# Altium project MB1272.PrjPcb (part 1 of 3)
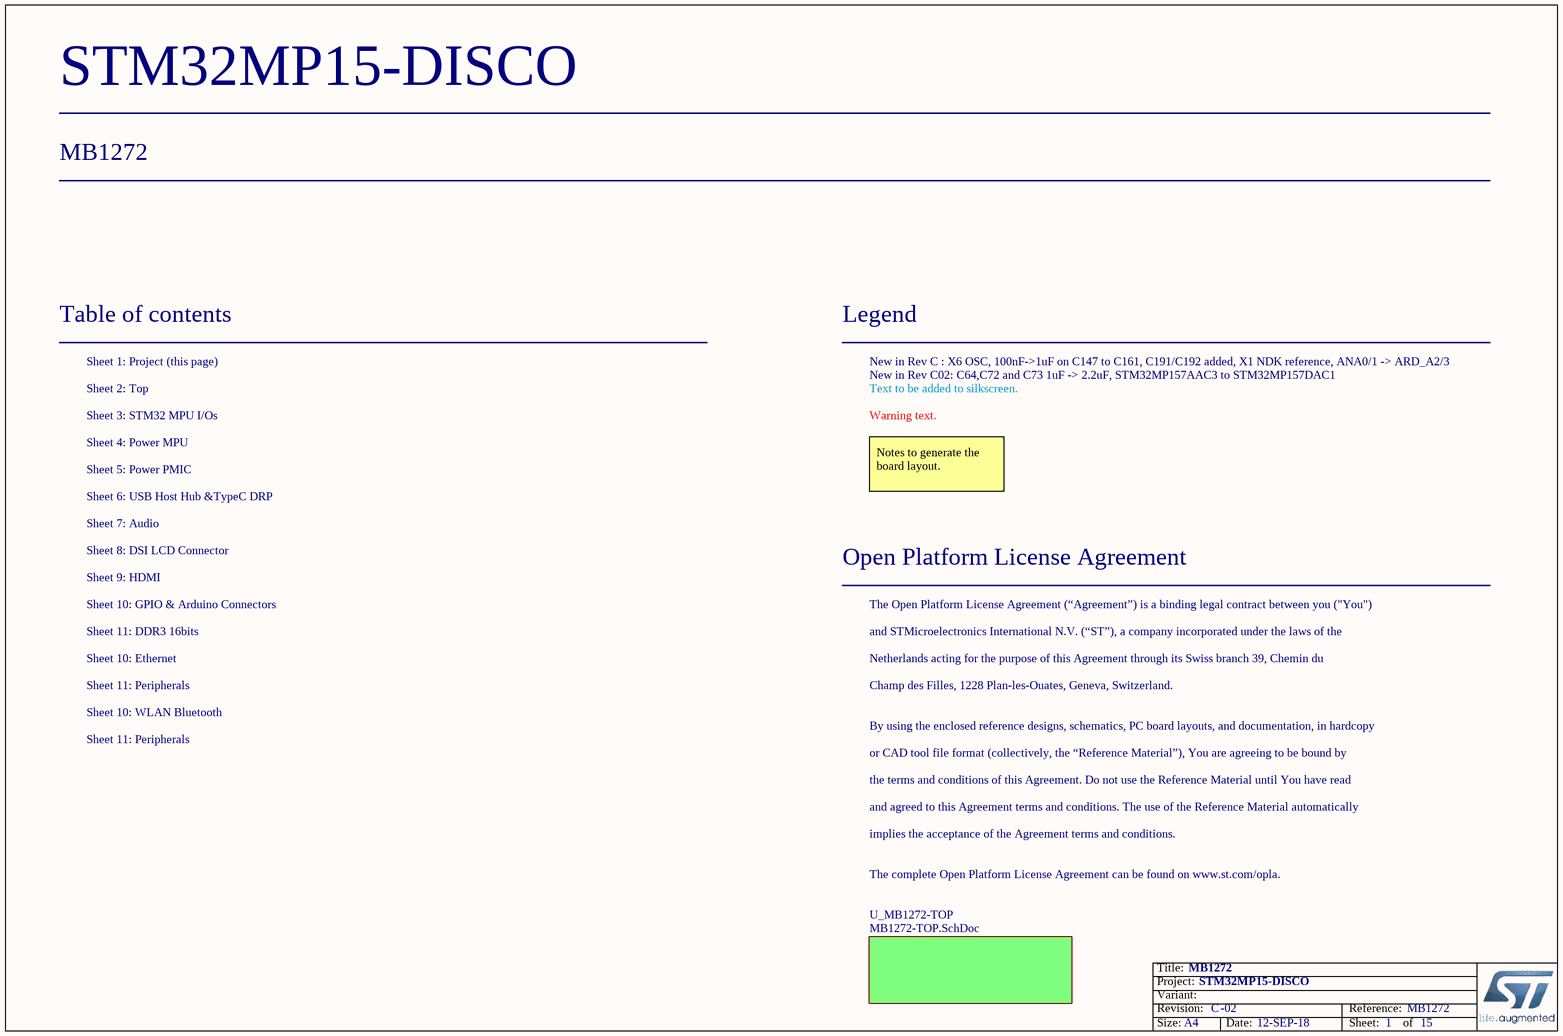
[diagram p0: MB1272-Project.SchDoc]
Board_Reference: MB1272; Board_PCB_Revision: C; Board_Name: STM32MP15-DISCO; Board_Document_Date: 12-SEP-18; Board_Assembly_Revision: 02
15 sheets, 519 parts. Net scope: flat (ports and power ports of the same name join across sheets).
Board file: MB1272C.PcbDoc
Sheets:
  MB1272-Project.SchDoc
    U_MB1272-TOP = MB1272-TOP.SchDoc
      U_Power_PMIC = Power_PMIC.SchDoc
      U_Power_MPU = Power_MPU.SchDoc
      U_MPU_12x12 = MPU_12x12.SchDoc
      U_Peripherals = Peripherals.SchDoc
      U_ST_LINK_V2-1 = ST_LINK_V2-1.SCHDOC
      U_GPIO_&_Arduino_ Connectors = GPIO_&_Arduino_ Connectors.SchDoc
      U_DSI_LCD = DSI_LCD.SchDoc
      U_WLAN_BLUETOOTH = WLAN_BLUETOOTH.SchDoc
      U_Ethernet = Ethernet.SchDoc
      U_HDMI = HDMI.SchDoc
      U_USB_Host_Hub&TypeC_DRP = USB_Host_Hub&TypeC_DRP.SchDoc
      U_AUDIO = AUDIO.SchDoc
      U_DDR3_16bits = DDR3_16bits.SchDoc

## Sheet MB1272-Project.SchDoc: MB1272
size A4; Date: Not used; ApprovedBy: Not used; CheckedBy: Not used; Author: Not used; CompanyName: STMicroelectronics; DrawnBy: Not used; Engineer: Not used; Organization: Not used; Address1: Not used; Address2: Not used; Address3: Not used; Address4: Not used; DocumentNumber: Not used; Revision: Not used; SheetNumber: 1; SheetTotal: 15

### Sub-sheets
U_MB1272-TOP = MB1272-TOP.SchDoc: no entries

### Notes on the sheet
- Table of contents
- Sheet 1: Project (this page)
- Legend
- New in Rev C : X6 OSC, 100nF->1uF on C147 to C161, C191/C192 added, X1 NDK reference, ANA0/1 -> ARD_A2/3
- New in Rev C02: C64,C72 and C73 1uF -> 2.2uF, STM32MP157AAC3 to STM32MP157DAC1
- Sheet 2: Top
- Sheet 3: STM32 MPU I/Os
- Sheet 4: Power MPU
- Text to be added to silkscreen.
- Warning text.
- Sheet 6: USB Host Hub &TypeC DRP
- Sheet 5: Power PMIC
- Notes to generate the board layout.
- Sheet 7: Audio
- Sheet 9: HDMI
- Sheet 8: DSI LCD Connector
- Open Platform License Agreement
- Sheet 10: GPIO & Arduino Connectors
- Sheet 11: DDR3 16bits
- The Open Platform License Agreement (“Agreement”) is a binding legal contract between you ("You")
- and STMicroelectronics International N.V. (“ST”), a company incorporated under the laws of the
- Sheet 10: Ethernet
- Sheet 11: Peripherals
- Sheet 10: WLAN Bluetooth
- Netherlands acting for the purpose of this Agreement through its Swiss branch 39, Chemin du
- Champ des Filles, 1228 Plan-les-Ouates, Geneva, Switzerland.
- By using the enclosed reference designs, schematics, PC board layouts, and documentation, in hardcopy
- or CAD tool file format (collectively, the “Reference Material”), You are agreeing to be bound by
- the terms and conditions of this Agreement. Do not use the Reference Material until You have read
- and agreed to this Agreement terms and conditions. The use of the Reference Material automatically
- implies the acceptance of the Agreement terms and conditions.
- The complete Open Platform License Agreement can be found on www.st.com/opla.

## Sheet MB1272-TOP.SchDoc: MB1272-TOP
size A4; CompanyName: STMicroelectronics; DocumentNumber: MB1272; Revision: B-01; SheetNumber: 2; SheetTotal: 15; Project: STM32MP15-DISCO PI
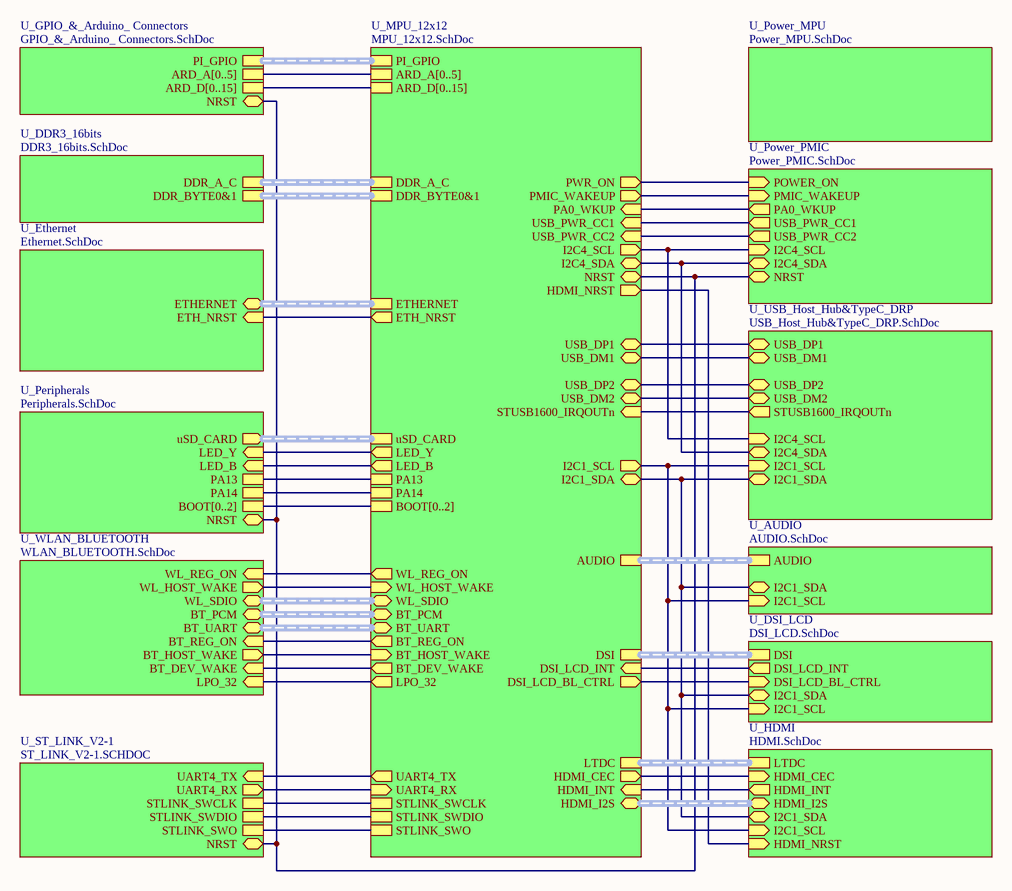
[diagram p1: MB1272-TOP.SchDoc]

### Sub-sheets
U_AUDIO = AUDIO.SchDoc: I2C1_SCL (in), I2C1_SDA (bidir), AUDIO (harness AUDIO)
U_DDR3_16bits = DDR3_16bits.SchDoc: DDR_A_C (harness DDR_A_C), DDR_BYTE0&1 (harness DDR_BYTE_0&1)
U_DSI_LCD = DSI_LCD.SchDoc: DSI (harness DSI), I2C1_SDA (bidir), I2C1_SCL (in), DSI_LCD_BL_CTRL (in), DSI_LCD_INT (out)
U_Ethernet = Ethernet.SchDoc: ETHERNET (harness ETHERNET), ETH_NRST (in)
U_GPIO_&_Arduino_ Connectors = GPIO_&_Arduino_ Connectors.SchDoc: NRST (bidir), ARD_A[0..5], ARD_D[0..15], PI_GPIO (harness PI_GPIO)
U_HDMI = HDMI.SchDoc: LTDC (harness LTDC), HDMI_CEC (in), I2C1_SDA (bidir), HDMI_INT (out), I2C1_SCL (in), HDMI_I2S (harness HDMI_I2S), HDMI_NRST (in)
U_MPU_12x12 = MPU_12x12.SchDoc: DDR_BYTE0&1 (harness DDR_BYTE_0&1), DDR_A_C (harness DDR_A_C), STLINK_SWDIO, STLINK_SWCLK, STLINK_SWO, UART4_TX (out), UART4_RX (in), PA13, PA14, PI_GPIO (harness PI_GPIO), ETHERNET (harness ETHERNET), AUDIO (harness AUDIO), PMIC_WAKEUP (out), PA0_WKUP (in), NRST (bidir), PWR_ON (out), I2C4_SCL (out), I2C4_SDA (bidir), DSI (harness DSI), LTDC (harness LTDC), HDMI_CEC (out), uSD_CARD (harness uSD_CARD), BOOT[0..2], ARD_A[0..5], ARD_D[0..15], I2C1_SDA (bidir), I2C1_SCL (out), USB_DM1 (bidir), USB_DM2 (bidir), USB_DP2 (bidir), USB_DP1 (bidir), DSI_LCD_BL_CTRL (out), DSI_LCD_INT (in), HDMI_INT (in), WL_SDIO (harness WLAN_SDIO), BT_PCM (harness BT_PCM), BT_UART (harness BT_UART), BT_REG_ON (out), BT_HOST_WAKE (in), WL_REG_ON (out), BT_DEV_WAKE (out), WL_HOST_WAKE (in), HDMI_I2S (harness HDMI_I2S), STUSB1600_IRQOUTn (in), LPO_32 (out), USB_PWR_CC1 (in), USB_PWR_CC2 (in), LED_Y (out), LED_B (out), HDMI_NRST (out), ETH_NRST (out)
U_Peripherals = Peripherals.SchDoc: BOOT[0..2], PA13, PA14, NRST (bidir), uSD_CARD (harness uSD_CARD), LED_B (in), LED_Y (in)
U_Power_MPU = Power_MPU.SchDoc: no entries
U_Power_PMIC = Power_PMIC.SchDoc: I2C4_SDA (bidir), I2C4_SCL (in), PA0_WKUP (out), NRST (bidir), POWER_ON (in), PMIC_WAKEUP (in), USB_PWR_CC1 (out), USB_PWR_CC2 (out)
U_ST_LINK_V2-1 = ST_LINK_V2-1.SCHDOC: NRST (bidir), STLINK_SWO, STLINK_SWDIO, STLINK_SWCLK, UART4_RX (out), UART4_TX (in)
U_USB_Host_Hub&TypeC_DRP = USB_Host_Hub&TypeC_DRP.SchDoc: USB_DP1 (bidir), USB_DM1 (bidir), I2C1_SDA (bidir), I2C1_SCL (in), STUSB1600_IRQOUTn (out), I2C4_SCL (in), I2C4_SDA (bidir), USB_DM2 (bidir), USB_DP2 (bidir)
U_WLAN_BLUETOOTH = WLAN_BLUETOOTH.SchDoc: WL_SDIO (harness WLAN_SDIO), BT_UART (harness BT_UART), BT_PCM (harness BT_PCM), BT_REG_ON (in), BT_HOST_WAKE (out), WL_REG_ON (in), BT_DEV_WAKE (in), WL_HOST_WAKE (out), LPO_32 (in)

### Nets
(unnamed): sheet U_Power_PMIC/I2C4_SDA, sheet U_MPU_12x12/I2C4_SDA, sheet U_USB_Host_Hub&TypeC_DRP/I2C4_SDA
(unnamed): sheet U_Power_PMIC/I2C4_SCL, sheet U_MPU_12x12/I2C4_SCL, sheet U_USB_Host_Hub&TypeC_DRP/I2C4_SCL  [a separate net that carries the same name]
(unnamed): sheet U_Power_PMIC/PA0_WKUP, sheet U_MPU_12x12/PA0_WKUP  [a separate net that carries the same name]
(unnamed): sheet U_Power_PMIC/NRST, sheet U_MPU_12x12/NRST, sheet U_Peripherals/NRST, sheet U_ST_LINK_V2-1/NRST, sheet U_GPIO_&_Arduino_ Connectors/NRST  [a separate net that carries the same name]
(unnamed): sheet U_Power_PMIC/POWER_ON, sheet U_MPU_12x12/PWR_ON  [a separate net that carries the same name]
(unnamed): sheet U_Power_PMIC/PMIC_WAKEUP, sheet U_MPU_12x12/PMIC_WAKEUP  [a separate net that carries the same name]
(unnamed): sheet U_Power_PMIC/USB_PWR_CC1, sheet U_MPU_12x12/USB_PWR_CC1  [a separate net that carries the same name]
(unnamed): sheet U_Power_PMIC/USB_PWR_CC2, sheet U_MPU_12x12/USB_PWR_CC2  [a separate net that carries the same name]
(unnamed): sheet U_MPU_12x12/STLINK_SWDIO, sheet U_ST_LINK_V2-1/STLINK_SWDIO  [a separate net that carries the same name]
(unnamed): sheet U_MPU_12x12/STLINK_SWCLK, sheet U_ST_LINK_V2-1/STLINK_SWCLK  [a separate net that carries the same name]
(unnamed): sheet U_MPU_12x12/STLINK_SWO, sheet U_ST_LINK_V2-1/STLINK_SWO  [a separate net that carries the same name]
(unnamed): sheet U_MPU_12x12/UART4_TX, sheet U_ST_LINK_V2-1/UART4_TX  [a separate net that carries the same name]
(unnamed): sheet U_MPU_12x12/UART4_RX, sheet U_ST_LINK_V2-1/UART4_RX  [a separate net that carries the same name]
(unnamed): sheet U_MPU_12x12/PA13, sheet U_Peripherals/PA13  [a separate net that carries the same name]
(unnamed): sheet U_MPU_12x12/PA14, sheet U_Peripherals/PA14  [a separate net that carries the same name]
(unnamed): sheet U_MPU_12x12/HDMI_CEC, sheet U_HDMI/HDMI_CEC  [a separate net that carries the same name]
(unnamed): sheet U_MPU_12x12/I2C1_SDA, sheet U_DSI_LCD/I2C1_SDA, sheet U_HDMI/I2C1_SDA, sheet U_USB_Host_Hub&TypeC_DRP/I2C1_SDA, sheet U_AUDIO/I2C1_SDA  [a separate net that carries the same name]
(unnamed): sheet U_MPU_12x12/I2C1_SCL, sheet U_DSI_LCD/I2C1_SCL, sheet U_HDMI/I2C1_SCL, sheet U_USB_Host_Hub&TypeC_DRP/I2C1_SCL, sheet U_AUDIO/I2C1_SCL  [a separate net that carries the same name]
(unnamed): sheet U_MPU_12x12/USB_DM1, sheet U_USB_Host_Hub&TypeC_DRP/USB_DM1  [a separate net that carries the same name]
(unnamed): sheet U_MPU_12x12/USB_DM2, sheet U_USB_Host_Hub&TypeC_DRP/USB_DM2  [a separate net that carries the same name]
(unnamed): sheet U_MPU_12x12/USB_DP2, sheet U_USB_Host_Hub&TypeC_DRP/USB_DP2  [a separate net that carries the same name]
(unnamed): sheet U_MPU_12x12/USB_DP1, sheet U_USB_Host_Hub&TypeC_DRP/USB_DP1  [a separate net that carries the same name]
(unnamed): sheet U_MPU_12x12/DSI_LCD_BL_CTRL, sheet U_DSI_LCD/DSI_LCD_BL_CTRL  [a separate net that carries the same name]
(unnamed): sheet U_MPU_12x12/DSI_LCD_INT, sheet U_DSI_LCD/DSI_LCD_INT  [a separate net that carries the same name]
(unnamed): sheet U_MPU_12x12/HDMI_INT, sheet U_HDMI/HDMI_INT  [a separate net that carries the same name]
(unnamed): sheet U_MPU_12x12/BT_REG_ON, sheet U_WLAN_BLUETOOTH/BT_REG_ON  [a separate net that carries the same name]
(unnamed): sheet U_MPU_12x12/BT_HOST_WAKE, sheet U_WLAN_BLUETOOTH/BT_HOST_WAKE  [a separate net that carries the same name]
(unnamed): sheet U_MPU_12x12/WL_REG_ON, sheet U_WLAN_BLUETOOTH/WL_REG_ON  [a separate net that carries the same name]
(unnamed): sheet U_MPU_12x12/BT_DEV_WAKE, sheet U_WLAN_BLUETOOTH/BT_DEV_WAKE  [a separate net that carries the same name]
(unnamed): sheet U_MPU_12x12/WL_HOST_WAKE, sheet U_WLAN_BLUETOOTH/WL_HOST_WAKE  [a separate net that carries the same name]
(unnamed): sheet U_MPU_12x12/STUSB1600_IRQOUTn, sheet U_USB_Host_Hub&TypeC_DRP/STUSB1600_IRQOUTn  [a separate net that carries the same name]
(unnamed): sheet U_MPU_12x12/LPO_32, sheet U_WLAN_BLUETOOTH/LPO_32  [a separate net that carries the same name]
(unnamed): sheet U_MPU_12x12/LED_Y, sheet U_Peripherals/LED_Y  [a separate net that carries the same name]
(unnamed): sheet U_MPU_12x12/LED_B, sheet U_Peripherals/LED_B  [a separate net that carries the same name]
(unnamed): sheet U_MPU_12x12/HDMI_NRST, sheet U_HDMI/HDMI_NRST  [a separate net that carries the same name]
(unnamed): sheet U_MPU_12x12/ETH_NRST, sheet U_Ethernet/ETH_NRST  [a separate net that carries the same name]

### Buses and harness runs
bus sheet U_GPIO_&_Arduino_ Connectors/ARD_A[0..5] = sheet U_MPU_12x12/ARD_A[0..5]
bus sheet U_GPIO_&_Arduino_ Connectors/ARD_D[0..15] = sheet U_MPU_12x12/ARD_D[0..15]
bus sheet U_MPU_12x12/BOOT[0..2] = sheet U_Peripherals/BOOT[0..2]
harness sheet U_AUDIO/AUDIO = sheet U_MPU_12x12/AUDIO
harness sheet U_DDR3_16bits/DDR_A_C = sheet U_MPU_12x12/DDR_A_C
harness sheet U_DDR3_16bits/DDR_BYTE0&1 = sheet U_MPU_12x12/DDR_BYTE0&1
harness sheet U_DSI_LCD/DSI = sheet U_MPU_12x12/DSI
harness sheet U_Ethernet/ETHERNET = sheet U_MPU_12x12/ETHERNET
harness sheet U_GPIO_&_Arduino_ Connectors/PI_GPIO = sheet U_MPU_12x12/PI_GPIO
harness sheet U_HDMI/HDMI_I2S = sheet U_MPU_12x12/HDMI_I2S
harness sheet U_HDMI/LTDC = sheet U_MPU_12x12/LTDC
harness sheet U_MPU_12x12/BT_PCM = sheet U_WLAN_BLUETOOTH/BT_PCM
harness sheet U_MPU_12x12/BT_UART = sheet U_WLAN_BLUETOOTH/BT_UART
harness sheet U_MPU_12x12/uSD_CARD = sheet U_Peripherals/uSD_CARD
harness sheet U_MPU_12x12/WL_SDIO = sheet U_WLAN_BLUETOOTH/WL_SDIO

## Sheet Power_PMIC.SchDoc: Power_PMIC
size A3; Date: 01-DEC-2013; CompanyName: STMicroelectronics; Organization: Microcontrollers Division; Address1: 12, Rue Jules HOROWITZ; Address2: 38019 Grenoble; Address3: FRANCE; DocumentNumber: MB1272; Revision: A-01; SheetNumber: 5; SheetTotal: 15; Project: STM32MP15-DISCO PI
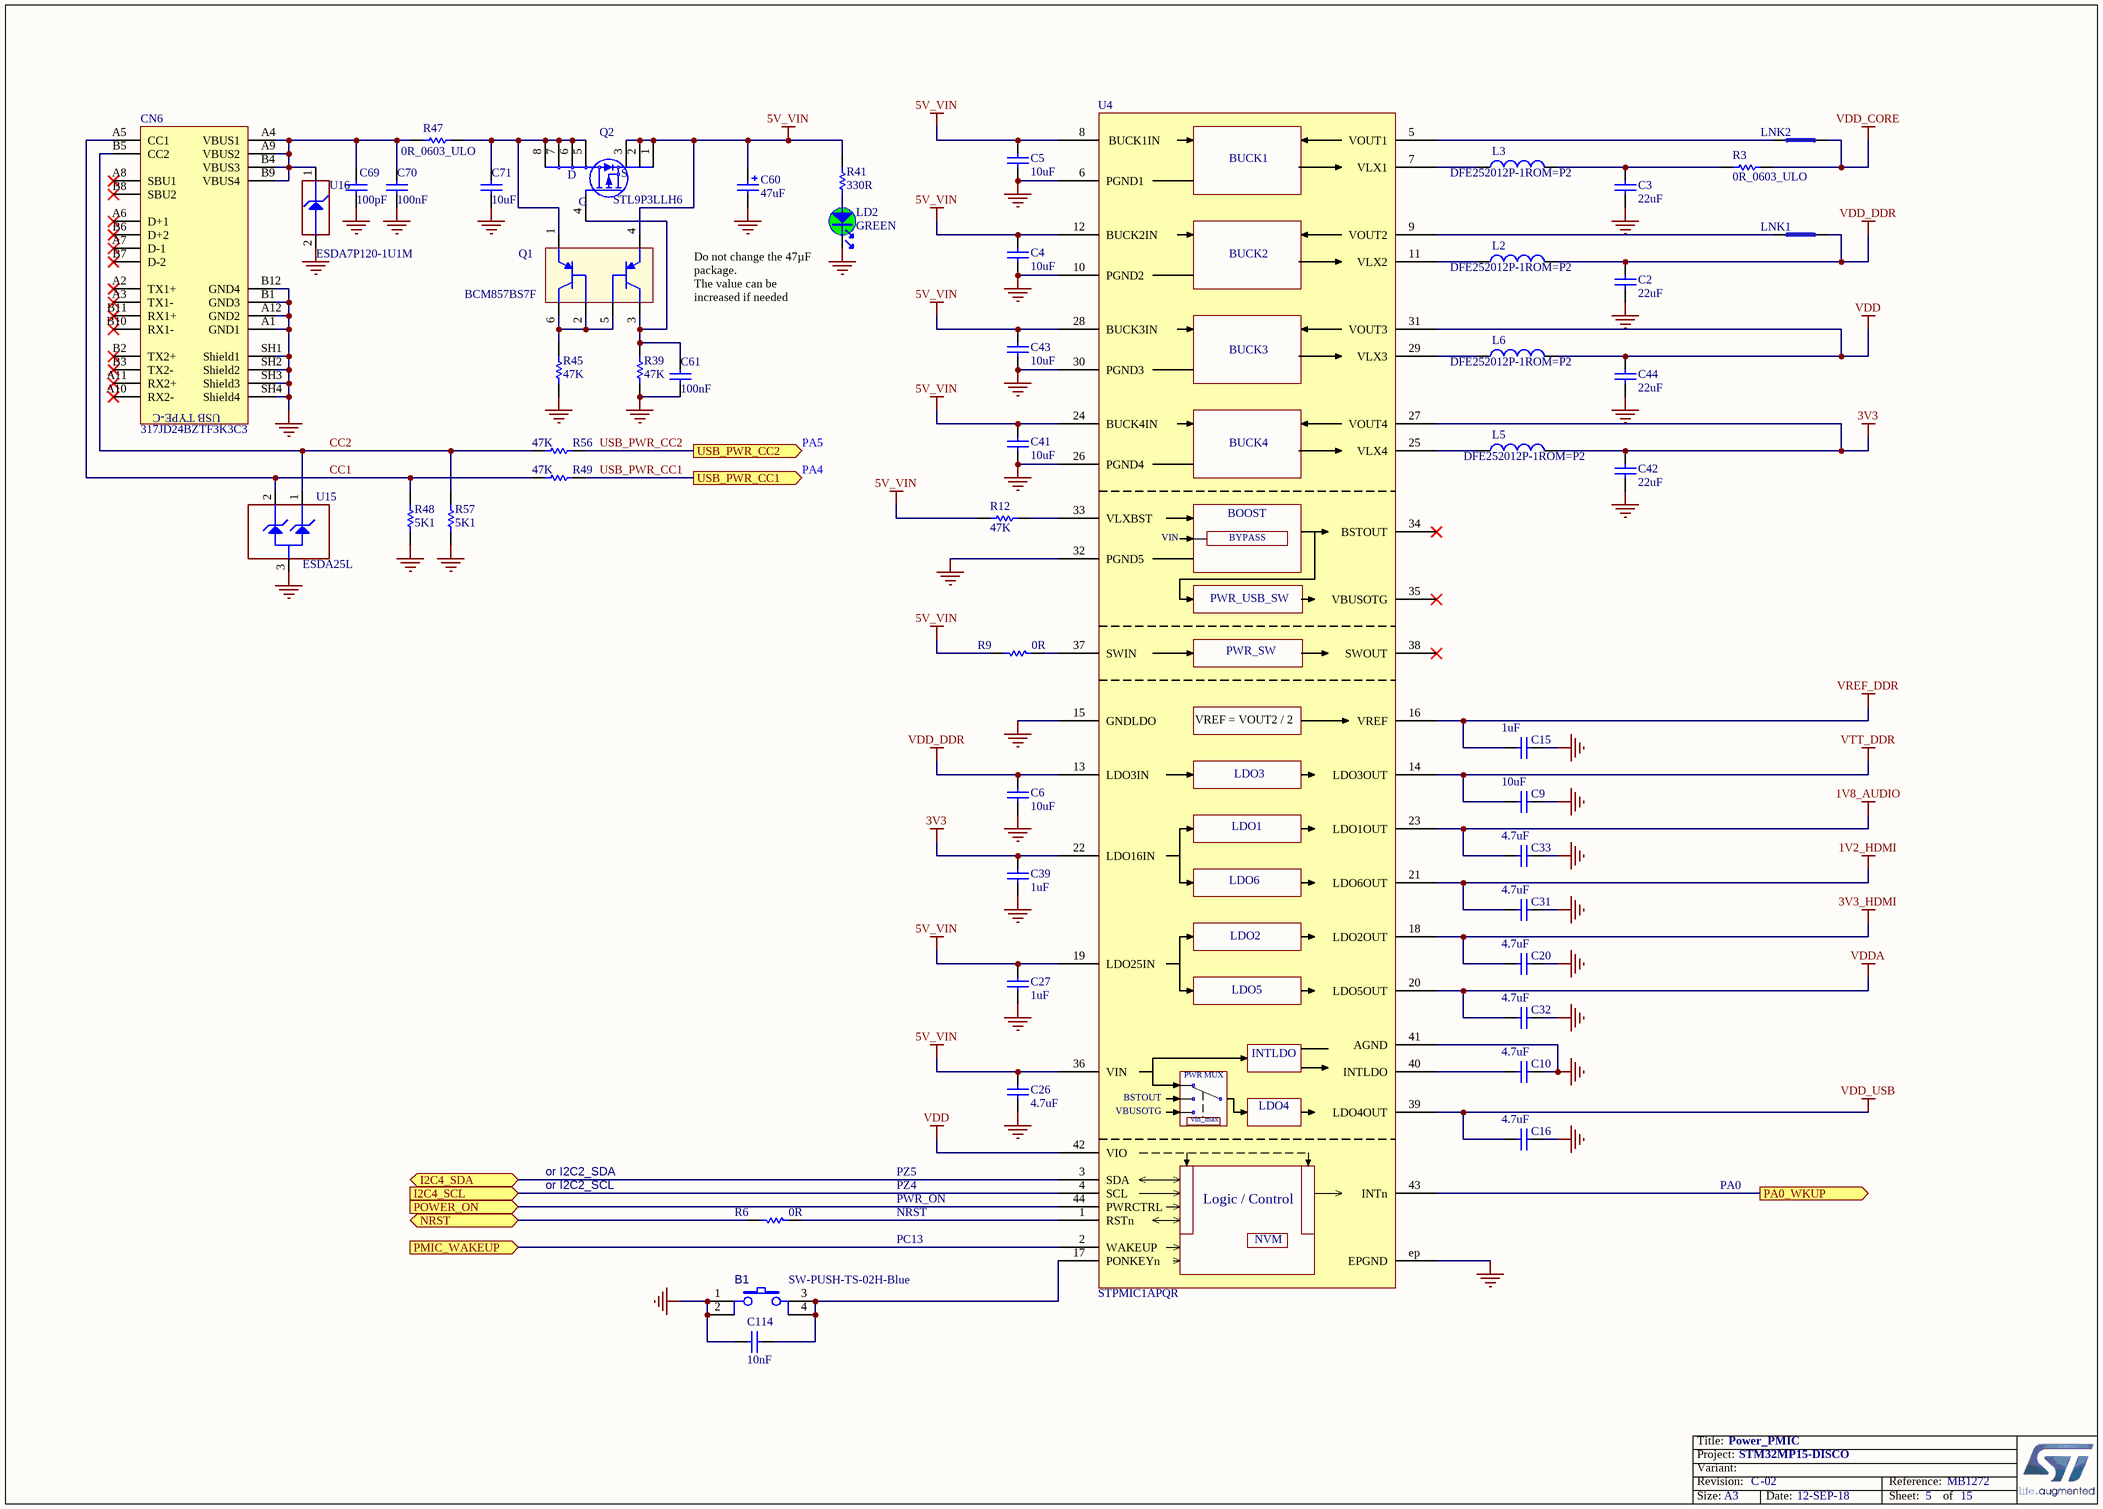
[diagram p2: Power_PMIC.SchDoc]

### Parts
B1  value SW-PUSH-TS-02H-Blue  [SWI_JIUBABA_C-TS-02H-2-5-B-V-T_R_BLUE]
C2  value 22uF  [C0603]
C3  value 22uF  [C0603]
C4  value 10uF  [C0603]
C5  value 10uF  [C0603]
C6  value 10uF  [C0603]
C9  value 10uF  [C0603]
C10  value 4.7uF  [C0402]  (hidden comment: Capacitor)
C15  value 1uF  [C0402]
C16  value 4.7uF  [C0402]  (hidden comment: Capacitor)
C20  value 4.7uF  [C0402]  (hidden comment: Capacitor)
C26  value 4.7uF  [C0402]  (hidden comment: Capacitor)
C27  value 1uF  [C0402]
C31  value 4.7uF  [C0402]  (hidden comment: Capacitor)
C32  value 4.7uF  [C0402]  (hidden comment: Capacitor)
C33  value 4.7uF  [C0402]  (hidden comment: Capacitor)
C39  value 1uF  [C0402]
C41  value 10uF  [C0603]
C42  value 22uF  [C0603]
C43  value 10uF  [C0603]
C44  value 22uF  [C0603]
C60  value 47uF  [CPOL_TAJ-C_2312_H2P6]  (hidden comment: Cap_POL_TANA)
C61  value 100nF  [C0402]
C69  value 100pF  [C0402]  (hidden comment: Capacitor)
C70  value 100nF  [C0402]
C71  value 10uF  [C0805]  (hidden comment: Capacitor)
C114  value 10nF  [C0402]
CN6  value 317JD24BZTF3K3C3  [CON_USB-TYPEC_COXOC_317JD24BZTF3K3C3]
L2  Manufacturer_Part_Number: DFE252012P-1ROM=P2  [IND_2520_TOKO_DFE252012P]  (hidden comment: IND_1uH_42mohm_3.2A)
L3  Manufacturer_Part_Number: DFE252012P-1ROM=P2  [IND_2520_TOKO_DFE252012P]  (hidden comment: IND_1uH_42mohm_3.2A)
L5  Manufacturer_Part_Number: DFE252012P-1ROM=P2  [IND_2520_TOKO_DFE252012P]  (hidden comment: IND_1uH_42mohm_3.2A)
L6  Manufacturer_Part_Number: DFE252012P-1ROM=P2  [IND_2520_TOKO_DFE252012P]  (hidden comment: IND_1uH_42mohm_3.2A)
LD2  value GREEN  [LED_0603_GREEN]
LNK1  link_200  [LINK200]  (value not drawn)  (no BOM)
LNK2  link_200  [LINK200]  (value not drawn)  (no BOM)
Q1  value BCM857BS7F  [DIO_SOT363]
Q2  value STL9P3LLH6  [MOS_POWERFLAT_3P3X3P3_P065]
R3  value 0R_0603_ULO  [R0603]
R6  value 0R  [R0402]
R9  value 0R  [R0402]
R12  value 47K  [R0402]  (hidden comment: Resistor)
R39  value 47K  [R0402]  (hidden comment: Resistor)
R41  value 330R  [R0402]
R45  value 47K  [R0402]  (hidden comment: Resistor)
R47  value 0R_0603_ULO  [R0603]
R48  value 5K1  [R0402]  (hidden comment: Resistor)
R49  value 47K  [R0402]  (hidden comment: Resistor)
R56  value 47K  [R0402]  (hidden comment: Resistor)
R57  value 5K1  [R0402]  (hidden comment: Resistor)
U4  value STPMIC1APQR  [ICC_WFQFN44-EPAD_5X6_P040]  (hidden comment: STPMU1)
U15  value ESDA25L  [ESD_SOT23]  (hidden comment: New schematic symbol : correction 2 diodes instead of one)
U16  value ESDA7P120-1U1M  [ESD_QFN1610_2N_1K_2A]  (hidden comment: ​Footprint needed DFN105P160X60-2N)

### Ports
I2C4_SCL (in), I2C4_SDA (bidir), NRST (bidir), PA0_WKUP (out), PMIC_WAKEUP (in), POWER_ON (in), USB_PWR_CC1 (out), USB_PWR_CC2 (out)

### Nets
1V2_HDMI: C31.2 U4.21(LDO6OUT)
1V8_AUDIO: C33.2 U4.23(LDO1OUT)
3V3: C39.2 C42.2 L5.2 U4.22(LDO16IN) U4.27(VOUT4)
3V3_HDMI: C20.2 U4.18(LDO2OUT)
5V_VIN: C4.2 C5.2 C26.2 C27.2 C41.2 C43.2 C60.1 Q1.4(E2) Q2.1(S) Q2.2(S) Q2.3(S) R9.1 R12.2 R41.2 U4.8(BUCK1IN) U4.12(BUCK2IN) U4.19(LDO25IN) U4.24(BUCK4IN) U4.28(BUCK3IN) U4.36(VIN)
GND: B1.1 B1.2 C2.1 C3.1 C4.1 C5.1 C6.1 C9.1 C10.2 C15.1 C16.1 C20.1 C26.1 C27.1 C31.1 C32.1 C33.1 C39.1 C41.1 C42.1 C43.1 C44.1 C60.2 C61.2 C69.1 C70.2 C71.1 C114.1 CN6.A1(GND1) CN6.A12(GND2) CN6.B1(GND3) CN6.B12(GND4) CN6.SH1(Shield1) CN6.SH2(Shield2) CN6.SH3(Shield3) CN6.SH4(Shield4) LD2.2 R39.1 R45.1 R48.1 R57.1 U4.6(PGND1) U4.10(PGND2) U4.15(GNDLDO) U4.26(PGND4) U4.30(PGND3) U4.32(PGND5) U4.41(AGND) U4.ep(EPGND) U15.3(GND) U16.2(GND)
VDD: C44.2 L6.2 U4.31(VOUT3) U4.42(VIO)
VDD_CORE: LNK2.2 R3.2
VDD_DDR: C2.2 C6.2 L2.2 LNK1.2 U4.13(LDO3IN)
VDD_USB: C16.2 U4.39(LDO4OUT)
VDDA: C32.2 U4.20(LDO5OUT)
VREF_DDR: C15.2 U4.16(VREF)
VTT_DDR: C9.2 U4.14(LDO3OUT)
CC1: CN6.A5(CC1) R48.2 R49.1 U15.2(IO2)
CC2: CN6.B5(CC2) R56.1 R57.2 U15.1(IO1)
I2C4_SCL: U4.4(SCL) ; port I2C4_SCL
I2C4_SDA: U4.3(SDA) ; port I2C4_SDA
NRST: R6.1 ; port NRST
PA0_WKUP: U4.43(INTn) ; port PA0_WKUP
PMIC_WAKEUP: U4.2(WAKEUP) ; port PMIC_WAKEUP
USB_PWR_CC1: R49.2 ; port USB_PWR_CC1
USB_PWR_CC2: R56.2 ; port USB_PWR_CC2
NetB1_3: B1.3 B1.4 C114.2 U4.17(PONKEYn)
NetC3_2: C3.2 L3.2 R3.1
NetC10_1: C10.1 U4.40(INTLDO)
NetC61_1: C61.1 Q1.3(C2) Q2.4(G) R39.2
NetC69_2: C69.2 C70.1 CN6.A4(VBUS1) CN6.A9(VBUS2) CN6.B4(VBUS3) CN6.B9(VBUS4) R47.1 U16.1(IO1)
NetC71_2: C71.2 Q1.1(E1) Q2.5(D) Q2.6(D) Q2.7(D) Q2.8(D) R47.2
NetL2_1: L2.1 U4.11(VLX2)
NetL3_1: L3.1 U4.7(VLX1)
NetL5_1: L5.1 U4.25(VLX4)
NetL6_1: L6.1 U4.29(VLX3)
NetLD2_1: LD2.1 R41.1
NetLNK1_1: LNK1.1 U4.9(VOUT2)
NetLNK2_1: LNK2.1 U4.5(VOUT1)
NetQ1_2: Q1.2(B1) Q1.5(B2) Q1.6(C1) R45.2
NetR6_2: R6.2 U4.1(RSTn)
NetR9_2: R9.2 U4.37(SWIN)
NetR12_1: R12.1 U4.33(VLXBST)
NetU4_44: U4.44(PWRCTRL) ; port POWER_ON

Not connected (* = marked no-connect by the designer): CN6 A2(TX1+)* A3(TX1-)* A6(D+1)* A7(D-1)* A8(SBU1)* A10(RX2-)* A11(RX2+)* B2(TX2+)* B3(TX2-)* B6(D+2)* B7(D-2)* B8(SBU2)* B10(RX1-)* B11(RX1+)*; U4 34(BSTOUT)* 35(VBUSOTG)* 38(SWOUT)*

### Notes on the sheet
- (near LD2) Do not change the 47µF package.
  The value can be increased if needed
- PA5
- PA4
- or I2C2_SDA
- or I2C2_SCL
- PZ5
- PZ4
- PA0
- NRST
- PWR_ON
- PC13

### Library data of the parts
B1 = MCD-00172: Switch HW SMD blue; Part_Type: Misc; Manufacturer_Part_Number: C-TS-02H-2.5-B-V-T/R BLUE; Manufacturer: JIUBABA; Provided_By: SUBCO; Initial_Board_Reference: MB1264
C2 C3 C42 C44 = MCD-00100: Capacitor, MLCC, 22uF, 6V3, X5R, 20%, 0603, T=0,8mm; Manufacturer_Part_Number: GRM188R60J226MEA0J; Manufacturer: MURATA; ECCN_US: EAR99; ECCN_EU: NEC; Provided_By: SUBCO; Initial_Board_Reference: mb1262
C4-C6 C9 C41 C43 = MCD-00099: Capacitor, MLCC, 10uF, 10V, X5R, 10%, 0603, T=0,8mm; Manufacturer_Part_Number: GRM188R61A106KE69D; Manufacturer: MURATA; ECCN_US: EAR99; ECCN_EU: NEC; Provided_By: SUBCO; Initial_Board_Reference: mb1262
C10 C16 C20 C26 C31-C33 = MCD-01356: Capacitor, MLCC, 4.7uF, 6V3, X5R, 20%, 0402, T=0,5mm; Manufacturer_Part_Number: GRM155R60J475ME47; Manufacturer: MURATA; Provided_By: SUBCO
C15 C27 C39 = MCD-00095: Capacitor, MLCC, 1uF, 6V3, X5R, 10%, 0402, T=0,5mm; Manufacturer_Part_Number: GRM155R61E105KA12; Manufacturer: MURATA; Alternate_Manufacturer_Part_Number: GRM155R60J105KE19; ECCN_US: EAR99; ECCN_EU: NEC; Provided_By: SUBCO; Initial_Board_Reference: mb1262
C60 = MCD-00559: Capacitor, Tantalum, 47uF, 16V, 10%, TypeC; Manufacturer_Part_Number: TAJC476K016RNJ; Manufacturer: AVX; Provided_By: SUBCO; Initial_Board_Reference: MB1331
C61 C70 = MCD-00006: Capacitor,100nF,16V,X7R,10%,0402; Manufacturer_Part_Number: CC0402KRX7R7BB104; Manufacturer: YAGEO; Alternate_Manufacturer: MURATA; Alternate_Manufacturer_Part_Number: GCM155R71C104KA55D; Provided_By: SUBCO; Initial_Board_Reference: mb1274
C69 = MCD-00205: Capacitor, MLCC, 100pF, 50V, NPO, 5%, 0402, T=0,5mm; Manufacturer_Part_Number: CC0402JRNPO9BN101; Manufacturer: YAGEO; Provided_By: SUBCO
C71 = MCD-00014: Capacitor, MLCC, 10uF, 25V, X5R, 10%, 0805, T=0,85mm; Manufacturer_Part_Number: CC0805KRX5R8BB106; Manufacturer: YAGEO; Provided_By: SUBCO; Initial_Board_Reference: MB1274
C114 = MCD-00011: Capacitor, MLCC, 10nF, 16V, X7R, 10%, 0402, T=0.5mm; Manufacturer_Part_Number: CC0402KRX7R7BB103; Manufacturer: YAGEO; Provided_By: SUBCO; Initial_Board_Reference: mb1274
CN6 = MCD-01108: USB tyce C certified receptacle for 1.6mm pcb height; Part_Type: Connector; Manufacturer: CHANT SINCERE (COXOC); ECCN_US: NA; Provided_By: SUBCO; Initial_Board_Reference: MB1272
L2 L3 L5 L6 = MCD-01122: Power Inductor ,1µH,4.3A max,+-20%,0.042ohm,2520; Manufacturer: MURATA; ECCN_US: EAR99; Provided_By: SUBCO; Initial_Board_Reference: MB1272
LD2 = MCD-00050: LED, Green, 0603; Part_Type: Display; Manufacturer_Part_Number: 19-213SYGC/S530-E2/TR8; Manufacturer: EVERLIGHT; ECCN_US: EAR99; ECCN_EU: NEC; Provided_By: SUBCO; Initial_Board_Reference: mb1274
LNK1 LNK2 = link_200: link 0.2mm
Q1 = MCD-01120: Transistor 45V Matched Pair PNP small Signal transistor in SOT363; Part_Type: IC; Manufacturer: DIODES_INC; Alternate_Manufacturer_Part_Number: NST45010MW6T1G; Alternate_Manufacturer: ONSEMI; Provided_By: SUBCO; Initial_Board_Reference: MB1272
Q2 = MCD-01126: Power Mosfet, P-channel,VDS -30V,RDS 12mohm typ,ID -9A; Part_Type: IC; Manufacturer: STMICROELECTRONICS; ECCN_US: EAR99; ECCN_EU: NEC; Provided_By: SUBCO with ST control; Initial_Board_Reference: MB1272
R3 R47 = MCD-00181: Resistor,0R,0603,ULO; Manufacturer_Part_Number: PMR03EZPJ000; Manufacturer: ROHM; Provided_By: SUBCO
R6 R9 = MCD-00052: Resistor,0R,0402,5%,1/16W; Manufacturer_Part_Number: RC0402JR-070RL; Manufacturer: YAGEO; Provided_By: SUBCO; Initial_Board_Reference: mb1274
R12 R39 R45 R49 R56 = MCD-00063: Resistor,47K,0402,1%,1/16W; Manufacturer_Part_Number: RC0402FR-0747KL; Manufacturer: YAGEO; Provided_By: SUBCO; Initial_Board_Reference: MB1274
R41 = MCD-00062: Resistor,330R,0402,1%,1/16W; Manufacturer_Part_Number: RC0402FR-07330RL; Manufacturer: YAGEO; Provided_By: SUBCO; Initial_Board_Reference: mb1274
R48 R57 = MCD-00333: Resistor,5K1,0402,1%,1/16W; Manufacturer_Part_Number: RC0402FR-075K1L; Manufacturer: YAGEO; Provided_By: SUBCO; Initial_Board_Reference: MB1272
U4 = MCD-01650: ST PMIC:  4 step-down + 1 advanced boost SMPS, 6 LDOs, 2 pwr switches, DDR Vref, NVM option 'A' for IO@3.3V; Part_Type: IC; Manufacturer: STMICROELECTRONICS; Provided_By: SUBCO with ST control
U15 = MCD-01125: DUAL TRANSIL ARRAY FOR ESD PROTECTION; Part_Type: Diode; Manufacturer: STMICROELECTRONICS; BMS_Part_Number: 9151131; ECCN_US: EAR99; ECCN_EU: NEC; Provided_By: SUBCO with ST control; Initial_Board_Reference: MB1272
U16 = MCD-01026: High power transient voltage suppressor; Part_Type: Diode; Manufacturer: STMICROELECTRONICS; BMS_Part_Number: 9179046; ECCN_US: EAR99; ECCN_EU: NEC; Provided_By: SUBCO with ST control; Initial_Board_Reference: MB1378

## Sheet Power_MPU.SchDoc: Power_MPU
size A3; CompanyName: STMicroelectronics; DocumentNumber: MB1272; Revision: A-01; SheetNumber: 4; SheetTotal: 15; Project: STM32MP15-DISCO PI
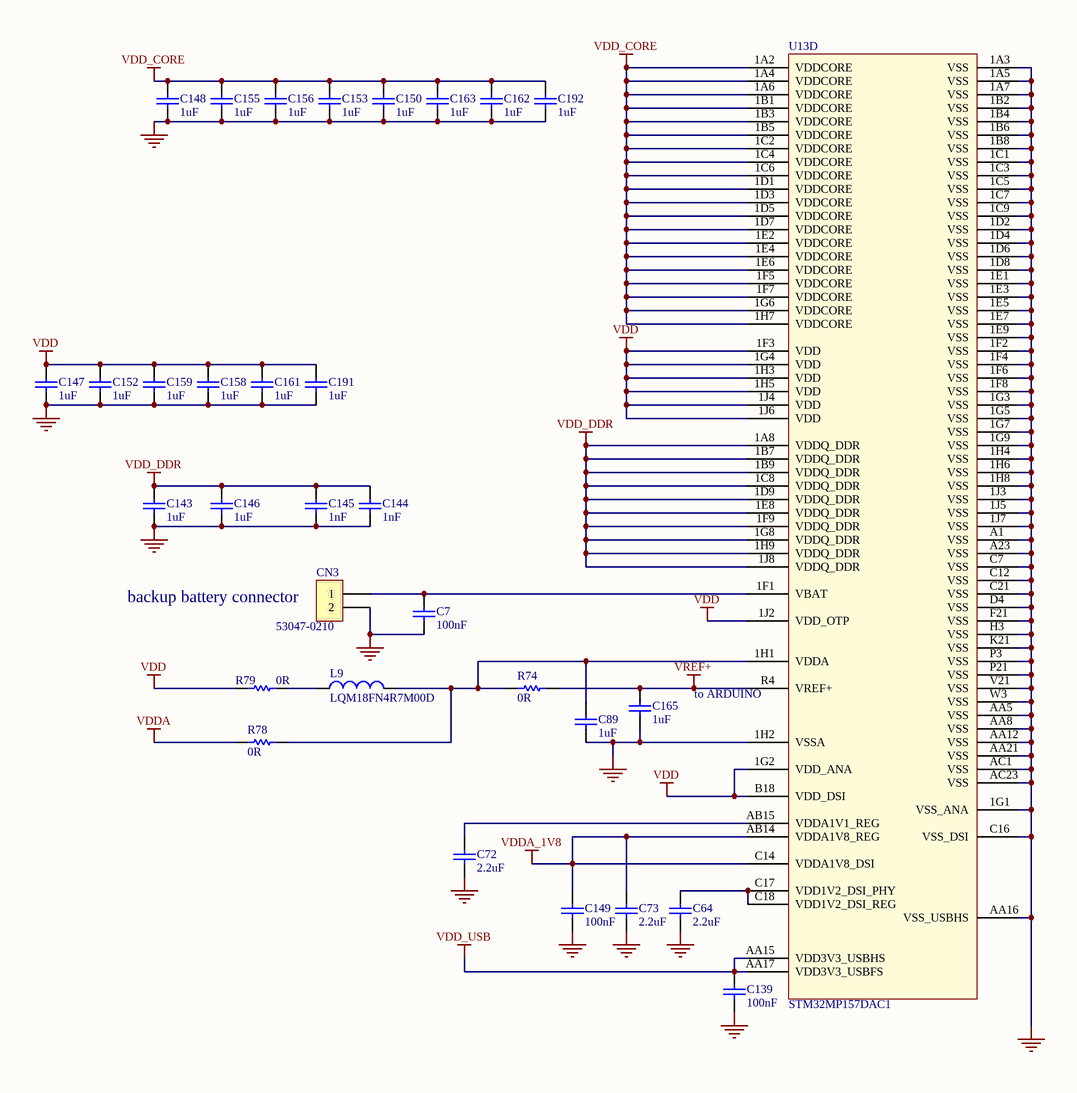
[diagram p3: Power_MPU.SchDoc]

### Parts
C7  value 100nF  [C0402]
C64  value 2.2uF  [C0402]  (hidden comment: Capacitor)
C72  value 2.2uF  [C0402]  (hidden comment: Capacitor)
C73  value 2.2uF  [C0402]  (hidden comment: Capacitor)
C89  value 1uF  [C0402]
C139  value 100nF  [C0402]
C143  value 1uF  [C0402]
C144  value 1nF  [C0402]
C145  value 1nF  [C0402]
C146  value 1uF  [C0402]
C147  value 1uF  [C0402]
C148  value 1uF  [C0402]
C149  value 100nF  [C0402]
C150  value 1uF  [C0402]
C152  value 1uF  [C0402]
C153  value 1uF  [C0402]
C155  value 1uF  [C0402]
C156  value 1uF  [C0402]
C158  value 1uF  [C0402]
C159  value 1uF  [C0402]
C161  value 1uF  [C0402]
C162  value 1uF  [C0402]
C163  value 1uF  [C0402]
C165  value 1uF  [C0402]
C191  value 1uF  [C0402]
C192  value 1uF  [C0402]
CN3  value 53047-0210  [CON_MOLEX_53047-0210]
L9  LQM18FN4R7M00D  [L0603]
R74  value 0R  [R0402]
R78  value 0R  [R0402]
R79  value 0R  [R0402]
U13  value STM32MP157DAC1  [ICC_TFBGA361_12X12_STM32MP157CAC3_P050-065]  (part D of 5)

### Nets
GND: C7.1 C64.2 C72.2 C73.2 C89.1 C139.1 C143.1 C144.1 C145.1 C146.1 C147.1 C148.1 C149.1 C150.1 C152.1 C153.1 C155.1 C156.1 C158.1 C159.1 C161.1 C162.1 C163.1 C165.1 C191.1 C192.1 CN3.2 U13.1A3(VSS) U13.1A5(VSS) U13.1A7(VSS) U13.1B2(VSS) U13.1B4(VSS) U13.1B6(VSS) U13.1B8(VSS) U13.1C1(VSS) U13.1C3(VSS) U13.1C5(VSS) U13.1C7(VSS) U13.1C9(VSS) U13.1D2(VSS) U13.1D4(VSS) U13.1D6(VSS) U13.1D8(VSS) U13.1E1(VSS) U13.1E3(VSS) U13.1E5(VSS) U13.1E7(VSS) U13.1E9(VSS) U13.1F2(VSS) U13.1F4(VSS) U13.1F6(VSS) U13.1F8(VSS) U13.1G1(VSS_ANA) U13.1G3(VSS) U13.1G5(VSS) U13.1G7(VSS) U13.1G9(VSS) U13.1H2(VSSA) U13.1H4(VSS) U13.1H6(VSS) U13.1H8(VSS) U13.1J3(VSS) U13.1J5(VSS) U13.1J7(VSS) U13.A1(VSS) U13.A23(VSS) U13.AA5(VSS) U13.AA8(VSS) U13.AA12(VSS) U13.AA16(VSS_USBHS) U13.AA21(VSS) U13.AC1(VSS) U13.AC23(VSS) U13.C7(VSS) U13.C12(VSS) U13.C16(VSS_DSI) U13.C21(VSS) U13.D4(VSS) U13.F21(VSS) U13.H3(VSS) U13.K21(VSS) U13.P3(VSS) U13.P21(VSS) U13.V21(VSS) U13.W3(VSS)
VDD: C147.2 C152.2 C158.2 C159.2 C161.2 C191.2 R79.1 U13.1F3(VDD) U13.1G2(VDD_ANA) U13.1G4(VDD) U13.1H3(VDD) U13.1H5(VDD) U13.1J2(VDD_OTP) U13.1J4(VDD) U13.1J6(VDD) U13.B18(VDD_DSI)
VDD_CORE: C148.2 C150.2 C153.2 C155.2 C156.2 C162.2 C163.2 C192.2 U13.1A2(VDDCORE) U13.1A4(VDDCORE) U13.1A6(VDDCORE) U13.1B1(VDDCORE) U13.1B3(VDDCORE) U13.1B5(VDDCORE) U13.1C2(VDDCORE) U13.1C4(VDDCORE) U13.1C6(VDDCORE) U13.1D1(VDDCORE) U13.1D3(VDDCORE) U13.1D5(VDDCORE) U13.1D7(VDDCORE) U13.1E2(VDDCORE) U13.1E4(VDDCORE) U13.1E6(VDDCORE) U13.1F5(VDDCORE) U13.1F7(VDDCORE) U13.1G6(VDDCORE) U13.1H7(VDDCORE)
VDD_DDR: C143.2 C144.2 C145.2 C146.2 U13.1A8(VDDQ_DDR) U13.1B7(VDDQ_DDR) U13.1B9(VDDQ_DDR) U13.1C8(VDDQ_DDR) U13.1D9(VDDQ_DDR) U13.1E8(VDDQ_DDR) U13.1F9(VDDQ_DDR) U13.1G8(VDDQ_DDR) U13.1H9(VDDQ_DDR) U13.1J8(VDDQ_DDR)
VDD_USB: C139.2 U13.AA15(VDD3V3_USBHS) U13.AA17(VDD3V3_USBFS)
VDDA: R78.1
VDDA_1V8: C73.1 C149.2 U13.AB14(VDDA1V8_REG) U13.C14(VDDA1V8_DSI)
VREF+: C165.2 R74.2 U13.R4(VREF+)
NetC7_2: C7.2 CN3.1 U13.1F1(VBAT)
NetC64_1: C64.1 U13.C17(VDD1V2_DSI_PHY) U13.C18(VDD1V2_DSI_REG)
NetC72_1: C72.1 U13.AB15(VDDA1V1_REG)
NetC89_2: C89.2 L9.2 R74.1 R78.2 U13.1H1(VDDA)
NetL9_1: L9.1 R79.2

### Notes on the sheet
- (near CN3) backup battery connector
- to ARDUINO

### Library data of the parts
C7 C139 C149 = MCD-00006: Capacitor,100nF,16V,X7R,10%,0402; Manufacturer_Part_Number: CC0402KRX7R7BB104; Manufacturer: YAGEO; Alternate_Manufacturer: MURATA; Alternate_Manufacturer_Part_Number: GCM155R71C104KA55D; Provided_By: SUBCO; Initial_Board_Reference: MB1274
C64 C72 C73 = MCD-01823: Capacitor,MLCC,2.2uF,6V3,X5R,10%,0402,T=0.5; Manufacturer_Part_Number: GRM155R60J225KE95D; Manufacturer: MURATA; ECCN_US: EAR99; ECCN_EU: NEC; Provided_By: SUBCO
C89 C143 C146-C148 C150 C152 C153 C155 C156 C158 C159 C161-C163 C165 C191 C192 = MCD-00095: Capacitor,1uF,6V3,X5R,10%,0402; Manufacturer_Part_Number: GRM155R61E105KA12; Manufacturer: MURATA; Alternate_Manufacturer_Part_Number: GRM155R60J105KE19; ECCN_US: EAR99; ECCN_EU: NEC; Provided_By: SUBCO; Initial_Board_Reference: MB1262
C144 C145 = MCD-00198: Capacitor,1nF,16V,X7R,10%,0402; Manufacturer_Part_Number: CC0402KRX7R7BB102; Manufacturer: YAGEO; Provided_By: SUBCO
CN3 = MCD-00655: Header 2 circuits, 1.25mm Pitch ,  Vertical, with Friction Lock; Part_Type: Connector; Manufacturer: MOLEX; Provided_By: SUBCO; Initial_Board_Reference: MB1272
L9 = MCD-01134: IND 4.7µH 20% 80mA 600mhom 0603; Part_Type: Inductor; Manufacturer: MURATA; Provided_By: SUBCO; Initial_Board_Reference: MB1272
R74 R78 = MCD-00052: Resistor,0R,0402,5%,1/16W; Manufacturer_Part_Number: RC0402JR-070RL; Manufacturer: YAGEO; Provided_By: SUBCO; Initial_Board_Reference: MB1274
R79 = MCD-00052: Resistor,0R,0402,5%,1/16W; Manufacturer_Part_Number: RC0402JR-070RL; Manufacturer: YAGEO; Provided_By: SUBCO; Initial_Board_Reference: MB1274; Fitted: NO
U13 = MCD-02020: MPU TFBGA12x12 without crypto increased frequency; Part_Type: IC; Manufacturer: STMICROELECTRONICS; Provided_By: SUBCO with ST control; ECCN_US: 3A991A2; ECCN_EU: NEC

## Sheet MPU_12x12.SchDoc: MPU_12x12
size A3; DocumentNumber: MB1272; Revision: A-01; SheetNumber: 3; SheetTotal: 15; Project: STM32MP15-DISCO PI
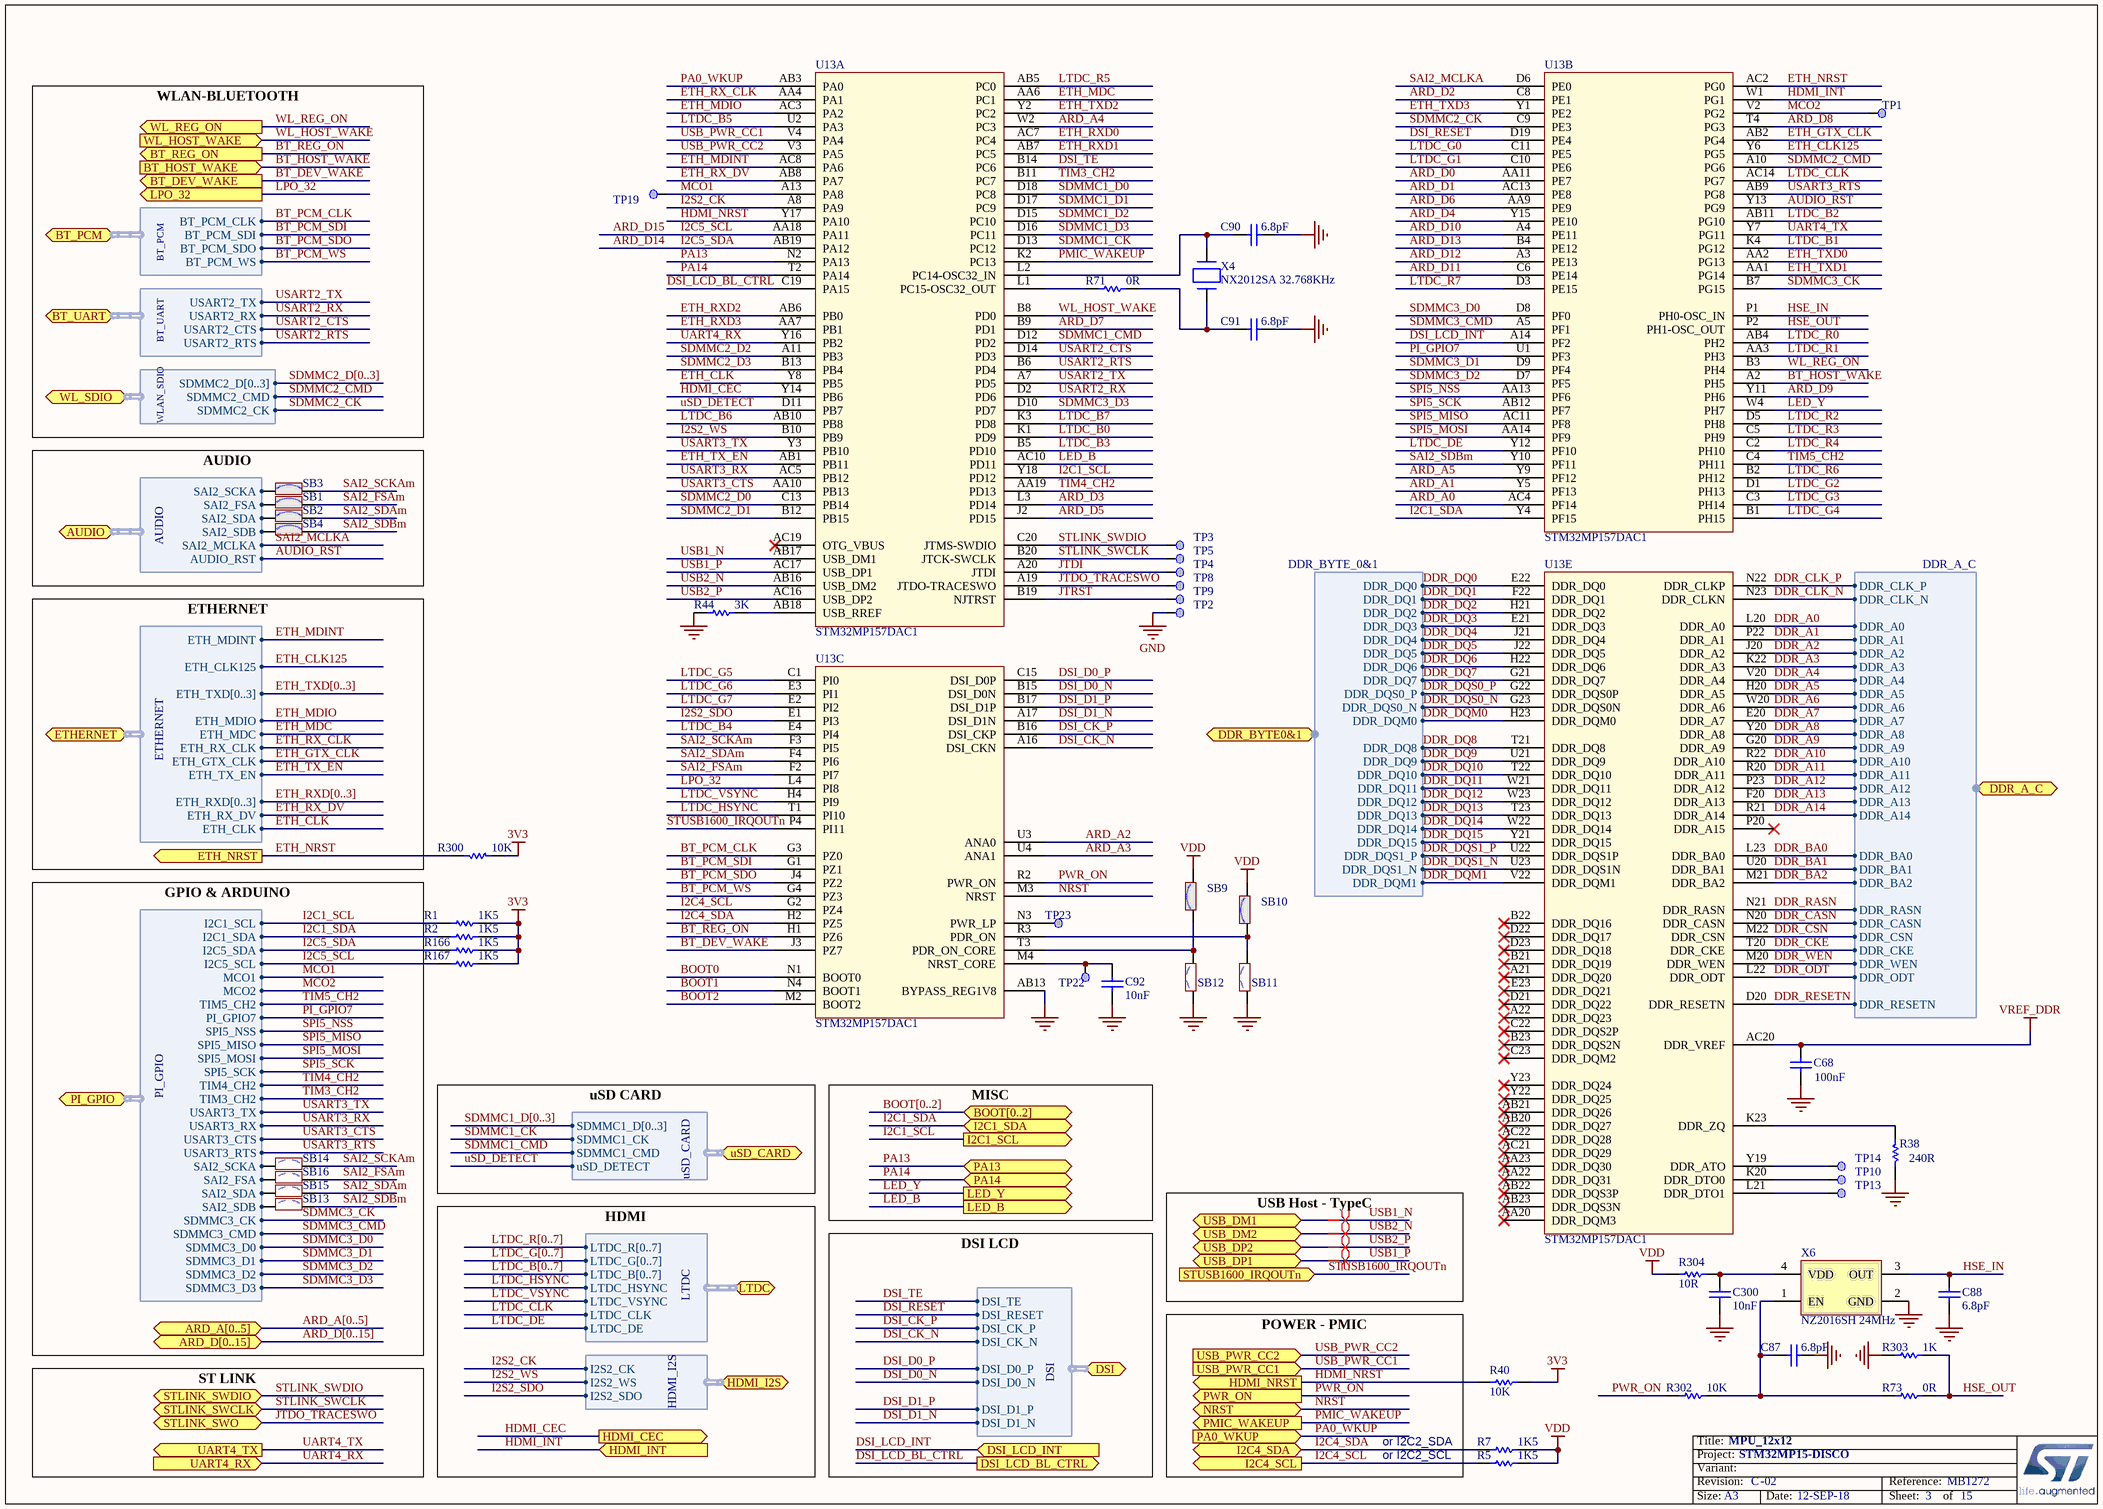
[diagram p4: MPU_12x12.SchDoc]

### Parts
C68  value 100nF  [C0402]
C87  value 6.8pF  [C0402]  (hidden comment: Capacitor)
C88  value 6.8pF  [C0402]  (hidden comment: Capacitor)
C90  value 6.8pF  [C0402]  (hidden comment: Capacitor)
C91  value 6.8pF  [C0402]  (hidden comment: Capacitor)
C92  value 10nF  [C0402]  (hidden comment: Capacitor)
C300  value 10nF  [C0402]  (hidden comment: Capacitor)
R1  value 1K5  [R0402]
R2  value 1K5  [R0402]
R5  value 1K5  [R0402]
R7  value 1K5  [R0402]
R38  value 240R  [R0402]
R40  value 10K  [R0402]  (hidden comment: Resistor)
R44  value 3K  [R0402]
R71  value 0R  [R0402]
R73  value 0R  [R0402]
R166  value 1K5  [R0402]
R167  value 1K5  [R0402]
R300  value 10K  [R0402]  (hidden comment: Resistor)
R302  value 10K  [R0402]  (hidden comment: Resistor)
R303  value 1K  [R0402]
R304  value 10R  [R0402]  (hidden comment: Resistor)
SB1  (no value)  [SOLDER-BRIDGE_R0603-0R]
SB2  (no value)  [SOLDER-BRIDGE_R0603-0R]
SB3  (no value)  [SOLDER-BRIDGE_R0603-0R]
SB4  (no value)  [SOLDER-BRIDGE_R0603-0R]
SB9  (no value)  [SOLDER-BRIDGE_R0603-0R]
SB10  (no value)  [SOLDER-BRIDGE_R0603-0R]
SB11  (no value)  [SOLDER-BRIDGE_R0603-0R]
SB12  (no value)  [SOLDER-BRIDGE_R0603-0R]
SB13  (no value)  [SOLDER-BRIDGE_R0603-0R]
SB14  (no value)  [SOLDER-BRIDGE_R0603-0R]
SB15  (no value)  [SOLDER-BRIDGE_R0603-0R]
SB16  (no value)  [SOLDER-BRIDGE_R0603-0R]
TP1  Test Point  [TP_SMD_1MM]  (value not drawn)  (no BOM)
TP2  Test Point  [TP_SMD_1MM]  (value not drawn)  (no BOM)
TP3  Test Point  [TP_SMD_1MM]  (value not drawn)  (no BOM)
TP4  Test Point  [TP_SMD_1MM]  (value not drawn)  (no BOM)
TP5  Test Point  [TP_SMD_1MM]  (value not drawn)  (no BOM)
TP8  Test Point  [TP_SMD_1MM]  (value not drawn)  (no BOM)
TP9  Test Point  [TP_SMD_1MM]  (value not drawn)  (no BOM)
TP10  (no value)  [TP_SMD_0-6MM]
TP13  (no value)  [TP_SMD_0-6MM]
TP14  (no value)  [TP_SMD_0-6MM]
TP19  Test Point  [TP_SMD_1MM]  (value not drawn)  (no BOM)
TP22  Test Point  [TP_SMD_1MM]  (value not drawn)  (no BOM)
TP23  Test Point  [TP_SMD_1MM]  (value not drawn)  (no BOM)
U13  value STM32MP157DAC1  [ICC_TFBGA361_12X12_STM32MP157CAC3_P050-065]  (parts A,B,C,E of 5)
X4  value NX2012SA 32.768KHz  [CRY_NX2012SA_2P]  (hidden comment: XTAL_2_PINS)
X6  value NZ2016SH 24MHz  [CRY_NZ2016SH_4P]  (hidden comment: OSCILLATOR_4_PINS)

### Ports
ARD_A[0..5], ARD_D[0..15], AUDIO (harness AUDIO), BOOT[0..2], BT_DEV_WAKE (out), BT_HOST_WAKE (in), BT_PCM (harness BT_PCM), BT_REG_ON (out), BT_UART (harness BT_UART), DDR_A_C (harness DDR_A_C), DDR_BYTE0&1 (harness DDR_BYTE_0&1), DSI (harness DSI), DSI_LCD_BL_CTRL (out), DSI_LCD_INT (in), ETH_NRST (out), ETHERNET (harness ETHERNET), HDMI_CEC (out), HDMI_I2S (harness HDMI_I2S), HDMI_INT (in), HDMI_NRST (out), I2C1_SCL (out), I2C1_SDA (bidir), I2C4_SCL (out), I2C4_SDA (bidir), LED_B (out), LED_Y (out), LPO_32 (out), LTDC (harness LTDC), NRST (bidir), PA0_WKUP (in), PA13, PA14, PI_GPIO (harness PI_GPIO), PMIC_WAKEUP (out), PWR_ON (out), STLINK_SWCLK, STLINK_SWDIO, STLINK_SWO, STUSB1600_IRQOUTn (in), UART4_RX (in), UART4_TX (out), USB_DM1 (bidir), USB_DM2 (bidir), USB_DP1 (bidir), USB_DP2 (bidir), USB_PWR_CC1 (in), USB_PWR_CC2 (in), uSD_CARD (harness uSD_CARD), WL_HOST_WAKE (in), WL_REG_ON (out), WL_SDIO (harness WLAN_SDIO)

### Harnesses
DDR_BYTE_0&1: DDR_DQ0, DDR_DQ1, DDR_DQ2, DDR_DQ3, DDR_DQ4, DDR_DQ5, DDR_DQ6, DDR_DQ7, DDR_DQS0_P, DDR_DQS0_N, DDR_DQM0, DDR_DQ8, DDR_DQ9, DDR_DQ10, DDR_DQ11, DDR_DQ12, DDR_DQ13, DDR_DQ14, DDR_DQ15, DDR_DQS1_P, DDR_DQS1_N, DDR_DQM1
DDR_A_C: DDR_CLK_P, DDR_CLK_N, DDR_A0, DDR_A1, DDR_A2, DDR_A3, DDR_A4, DDR_A5, DDR_A6, DDR_A7, DDR_A8, DDR_A9, DDR_A10, DDR_A11, DDR_A12, DDR_A13, DDR_A14, DDR_BA0, DDR_BA1, DDR_BA2, DDR_RASN, DDR_CASN, DDR_CSN, DDR_CKE, DDR_WEN, DDR_ODT, DDR_RESETN
PI_GPIO: I2C1_SCL, I2C1_SDA, I2C5_SDA, MCO1, MCO2, TIM5_CH2, PI_GPIO7, SPI5_NSS, SPI5_MISO, SPI5_MOSI, SPI5_SCK, TIM4_CH2, TIM3_CH2, USART3_TX, USART3_RX, USART3_CTS, USART3_RTS, SDMMC3_CK, SDMMC3_CMD, SDMMC3_D0, SDMMC3_D1, SDMMC3_D2, SDMMC3_D3, I2C5_SCL, SAI2_SCKA, SAI2_FSA, SAI2_SDA, SAI2_SDB
ETHERNET: ETH_MDINT, ETH_CLK125, ETH_TXD[0..3], ETH_MDIO, ETH_MDC, ETH_RX_CLK, ETH_GTX_CLK, ETH_TX_EN, ETH_RXD[0..3], ETH_RX_DV, ETH_CLK
AUDIO: SAI2_SCKA, SAI2_FSA, SAI2_SDA, SAI2_SDB, SAI2_MCLKA, AUDIO_RST
LTDC: LTDC_R[0..7], LTDC_G[0..7], LTDC_B[0..7], LTDC_HSYNC, LTDC_VSYNC, LTDC_CLK, LTDC_DE
uSD_CARD: SDMMC1_D[0..3], SDMMC1_CK, SDMMC1_CMD, uSD_DETECT
BT_PCM: BT_PCM_CLK, BT_PCM_SDI, BT_PCM_SDO, BT_PCM_WS
BT_UART: USART2_TX, USART2_RX, USART2_CTS, USART2_RTS
WLAN_SDIO: SDMMC2_D[0..3], SDMMC2_CMD, SDMMC2_CK
HDMI_I2S: I2S2_CK, I2S2_SDO, I2S2_WS
DSI: DSI_CK_P, DSI_CK_N, DSI_D0_P, DSI_D0_N, DSI_D1_P, DSI_D1_N, DSI_TE, DSI_RESET

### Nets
3V3: R1.1 R2.1 R40.1 R166.1 R167.1 R300.1
GND: C68.1 C87.2 C88.1 C90.2 C91.2 C92.1 C300.1 R38.2 R44.1 R303.2 SB11.1 SB12.1 TP2.1 U13.AB13(BYPASS_REG1V8) X6.2(GND)
VDD: R5.1 R7.1 R304.1 SB9.2 SB10.2
VREF_DDR: C68.2 U13.AC20(DDR_VREF)
ARD_A0: U13.AC4(PF14)
ARD_A1: U13.Y5(PF13)
ARD_A2: U13.U3(ANA0)
ARD_A3: U13.U4(ANA1)
ARD_A4: U13.W2(PC3)
ARD_A5: U13.Y9(PF12)
ARD_D0: U13.AA11(PE7)
ARD_D1: U13.AC13(PE8)
ARD_D2: U13.C8(PE1)
ARD_D3: U13.L3(PD14)
ARD_D4: U13.Y15(PE10)
ARD_D5: U13.J2(PD15)
ARD_D6: U13.AA9(PE9)
ARD_D7: U13.B9(PD1)
ARD_D8: U13.T4(PG3)
ARD_D9: U13.Y11(PH6)
ARD_D10: U13.A4(PE11)
ARD_D11: U13.C6(PE14)
ARD_D12: U13.A3(PE13)
ARD_D13: U13.B4(PE12)
ARD_D14: R166.2 U13.AB19(PA12) ; port PI_GPIO.I2C5_SDA  [also labelled I2C5_SDA]
ARD_D15: R167.2 U13.AA18(PA11) ; port PI_GPIO.I2C5_SCL  [also labelled I2C5_SCL]
AUDIO_RST: U13.Y13(PG9) ; port AUDIO.AUDIO_RST
BOOT0: U13.N1(BOOT0)
BOOT1: U13.N4(BOOT1)
BOOT2: U13.M2(BOOT2)
BT_DEV_WAKE: U13.J3(PZ7) ; port BT_DEV_WAKE
BT_HOST_WAKE: U13.A2(PH5) ; port BT_HOST_WAKE
BT_PCM_CLK: U13.G3(PZ0) ; port BT_PCM.BT_PCM_CLK
BT_PCM_SDI: U13.G1(PZ1) ; port BT_PCM.BT_PCM_SDI
BT_PCM_SDO: U13.J4(PZ2) ; port BT_PCM.BT_PCM_SDO
BT_PCM_WS: U13.G4(PZ3) ; port BT_PCM.BT_PCM_WS
BT_REG_ON: U13.H1(PZ6) ; port BT_REG_ON
DDR_A0: U13.L20(DDR_A0) ; port DDR_A_C.DDR_A0
DDR_A1: U13.P22(DDR_A1) ; port DDR_A_C.DDR_A1
DDR_A2: U13.J20(DDR_A2) ; port DDR_A_C.DDR_A2
DDR_A3: U13.K22(DDR_A3) ; port DDR_A_C.DDR_A3
DDR_A4: U13.V20(DDR_A4) ; port DDR_A_C.DDR_A4
DDR_A5: U13.H20(DDR_A5) ; port DDR_A_C.DDR_A5
DDR_A6: U13.W20(DDR_A6) ; port DDR_A_C.DDR_A6
DDR_A7: U13.E20(DDR_A7) ; port DDR_A_C.DDR_A7
DDR_A8: U13.Y20(DDR_A8) ; port DDR_A_C.DDR_A8
DDR_A9: U13.G20(DDR_A9) ; port DDR_A_C.DDR_A9
DDR_A10: U13.R22(DDR_A10) ; port DDR_A_C.DDR_A10
DDR_A11: U13.R20(DDR_A11) ; port DDR_A_C.DDR_A11
DDR_A12: U13.P23(DDR_A12) ; port DDR_A_C.DDR_A12
DDR_A13: U13.F20(DDR_A13) ; port DDR_A_C.DDR_A13
DDR_A14: U13.R21(DDR_A14) ; port DDR_A_C.DDR_A14
DDR_BA0: U13.L23(DDR_BA0) ; port DDR_A_C.DDR_BA0
DDR_BA1: U13.U20(DDR_BA1) ; port DDR_A_C.DDR_BA1
DDR_BA2: U13.M21(DDR_BA2) ; port DDR_A_C.DDR_BA2
DDR_CASN: U13.N20(DDR_CASN) ; port DDR_A_C.DDR_CASN
DDR_CKE: U13.T20(DDR_CKE) ; port DDR_A_C.DDR_CKE
DDR_CLK_N: U13.N23(DDR_CLKN) ; port DDR_A_C.DDR_CLK_N
DDR_CLK_P: U13.N22(DDR_CLKP) ; port DDR_A_C.DDR_CLK_P
DDR_CSN: U13.M22(DDR_CSN) ; port DDR_A_C.DDR_CSN
DDR_DQ0: U13.E22(DDR_DQ0) ; port DDR_BYTE0&1.DDR_DQ0
DDR_DQ1: U13.F22(DDR_DQ1) ; port DDR_BYTE0&1.DDR_DQ1
DDR_DQ2: U13.H21(DDR_DQ2) ; port DDR_BYTE0&1.DDR_DQ2
DDR_DQ3: U13.E21(DDR_DQ3) ; port DDR_BYTE0&1.DDR_DQ3
DDR_DQ4: U13.J21(DDR_DQ4) ; port DDR_BYTE0&1.DDR_DQ4
DDR_DQ5: U13.J22(DDR_DQ5) ; port DDR_BYTE0&1.DDR_DQ5
DDR_DQ6: U13.H22(DDR_DQ6) ; port DDR_BYTE0&1.DDR_DQ6
DDR_DQ7: U13.G21(DDR_DQ7) ; port DDR_BYTE0&1.DDR_DQ7
DDR_DQ8: U13.T21(DDR_DQ8) ; port DDR_BYTE0&1.DDR_DQ8
DDR_DQ9: U13.U21(DDR_DQ9) ; port DDR_BYTE0&1.DDR_DQ9
DDR_DQ10: U13.T22(DDR_DQ10) ; port DDR_BYTE0&1.DDR_DQ10
DDR_DQ11: U13.W21(DDR_DQ11) ; port DDR_BYTE0&1.DDR_DQ11
DDR_DQ12: U13.W23(DDR_DQ12) ; port DDR_BYTE0&1.DDR_DQ12
DDR_DQ13: U13.T23(DDR_DQ13) ; port DDR_BYTE0&1.DDR_DQ13
DDR_DQ14: U13.W22(DDR_DQ14) ; port DDR_BYTE0&1.DDR_DQ14
DDR_DQ15: U13.Y21(DDR_DQ15) ; port DDR_BYTE0&1.DDR_DQ15
DDR_DQM0: U13.H23(DDR_DQM0) ; port DDR_BYTE0&1.DDR_DQM0
DDR_DQM1: U13.V22(DDR_DQM1) ; port DDR_BYTE0&1.DDR_DQM1
DDR_DQS0_N: U13.G23(DDR_DQS0N) ; port DDR_BYTE0&1.DDR_DQS0_N
DDR_DQS0_P: U13.G22(DDR_DQS0P) ; port DDR_BYTE0&1.DDR_DQS0_P
DDR_DQS1_N: U13.U23(DDR_DQS1N) ; port DDR_BYTE0&1.DDR_DQS1_N
DDR_DQS1_P: U13.U22(DDR_DQS1P) ; port DDR_BYTE0&1.DDR_DQS1_P
DDR_ODT: U13.L22(DDR_ODT) ; port DDR_A_C.DDR_ODT
DDR_RASN: U13.N21(DDR_RASN) ; port DDR_A_C.DDR_RASN
DDR_RESETN: U13.D20(DDR_RESETN) ; port DDR_A_C.DDR_RESETN
DDR_WEN: U13.M20(DDR_WEN) ; port DDR_A_C.DDR_WEN
DSI_CK_N: U13.A16(DSI_CKN) ; port DSI.DSI_CK_N
DSI_CK_P: U13.B16(DSI_CKP) ; port DSI.DSI_CK_P
DSI_D0_N: U13.B15(DSI_D0N) ; port DSI.DSI_D0_N
DSI_D0_P: U13.C15(DSI_D0P) ; port DSI.DSI_D0_P
DSI_D1_N: U13.A17(DSI_D1N) ; port DSI.DSI_D1_N
DSI_D1_P: U13.B17(DSI_D1P) ; port DSI.DSI_D1_P
DSI_LCD_BL_CTRL: U13.C19(PA15) ; port DSI_LCD_BL_CTRL
DSI_LCD_INT: U13.A14(PF2) ; port DSI_LCD_INT
DSI_RESET: U13.D19(PE4) ; port DSI.DSI_RESET
DSI_TE: U13.B14(PC6) ; port DSI.DSI_TE
ETH_CLK: U13.Y8(PB5) ; port ETHERNET.ETH_CLK
ETH_CLK125: U13.Y6(PG5) ; port ETHERNET.ETH_CLK125
ETH_GTX_CLK: U13.AB2(PG4) ; port ETHERNET.ETH_GTX_CLK
ETH_MDC: U13.AA6(PC1) ; port ETHERNET.ETH_MDC
ETH_MDINT: U13.AC8(PA6) ; port ETHERNET.ETH_MDINT
ETH_MDIO: U13.AC3(PA2) ; port ETHERNET.ETH_MDIO
ETH_NRST: R300.2 U13.AC2(PG0) ; port ETH_NRST
ETH_RX_CLK: U13.AA4(PA1) ; port ETHERNET.ETH_RX_CLK
ETH_RX_DV: U13.AB8(PA7) ; port ETHERNET.ETH_RX_DV
ETH_RXD0: U13.AC7(PC4)
ETH_RXD1: U13.AB7(PC5)
ETH_RXD2: U13.AB6(PB0)
ETH_RXD3: U13.AA7(PB1)
ETH_TX_EN: U13.AB1(PB11) ; port ETHERNET.ETH_TX_EN
ETH_TXD0: U13.AA2(PG13)
ETH_TXD1: U13.AA1(PG14)
ETH_TXD2: U13.Y2(PC2)
ETH_TXD3: U13.Y1(PE2)
EXP_GPIO18: SB14.1 ; port PI_GPIO.SAI2_SCKA
EXP_GPIO19: SB16.1 ; port PI_GPIO.SAI2_FSA
EXP_GPIO20: SB15.1 ; port PI_GPIO.SAI2_SDA
EXP_GPIO21: SB13.1 ; port PI_GPIO.SAI2_SDB
HDMI_CEC: U13.Y14(PB6) ; port HDMI_CEC
HDMI_INT: U13.W1(PG1) ; port HDMI_INT
HDMI_NRST: R40.2 U13.Y17(PA10) ; port HDMI_NRST
HSE_IN: C88.2 U13.P1(PH0-OSC_IN) X6.3(OUT)
HSE_OUT: R73.2 R303.1 U13.P2(PH1-OSC_OUT)
I2C1_SCL: R1.2 U13.Y18(PD12) ; port I2C1_SCL, port PI_GPIO.I2C1_SCL
I2C1_SDA: R2.2 U13.Y4(PF15) ; port I2C1_SDA, port PI_GPIO.I2C1_SDA
I2C4_SCL: R5.2 U13.G2(PZ4) ; port I2C4_SCL
I2C4_SDA: R7.2 U13.H2(PZ5) ; port I2C4_SDA
I2S2_CK: U13.A8(PA9) ; port HDMI_I2S.I2S2_CK
I2S2_SDO: U13.E1(PI3) ; port HDMI_I2S.I2S2_SDO
I2S2_WS: U13.B10(PB9) ; port HDMI_I2S.I2S2_WS
JTDI: TP4.1 U13.A20(JTDI)
JTDO_TRACESWO: TP8.1 U13.A19(JTDO-TRACESWO) ; port STLINK_SWO
JTRST: TP9.1 U13.B19(NJTRST)
LED_B: U13.AC10(PD11) ; port LED_B
LED_Y: U13.W4(PH7) ; port LED_Y
LPO_32: U13.L4(PI8) ; port LPO_32
LTDC_B0: U13.K1(PD9)
LTDC_B1: U13.K4(PG12)
LTDC_B2: U13.AB11(PG10)
LTDC_B3: U13.B5(PD10)
LTDC_B4: U13.E4(PI4)
LTDC_B5: U13.U2(PA3)
LTDC_B6: U13.AB10(PB8)
LTDC_B7: U13.K3(PD8)
LTDC_CLK: U13.AC14(PG7) ; port LTDC.LTDC_CLK
LTDC_DE: U13.Y12(PF10) ; port LTDC.LTDC_DE
LTDC_G0: U13.C11(PE5)
LTDC_G1: U13.C10(PE6)
LTDC_G2: U13.D1(PH13)
LTDC_G3: U13.C3(PH14)
LTDC_G4: U13.B1(PH15)
LTDC_G5: U13.C1(PI0)
LTDC_G6: U13.E3(PI1)
LTDC_G7: U13.E2(PI2)
LTDC_HSYNC: U13.T1(PI10) ; port LTDC.LTDC_HSYNC
LTDC_R0: U13.AB4(PH2)
LTDC_R1: U13.AA3(PH3)
LTDC_R2: U13.D5(PH8)
LTDC_R3: U13.C5(PH9)
LTDC_R4: U13.C2(PH10)
LTDC_R5: U13.AB5(PC0)
LTDC_R6: U13.B2(PH12)
LTDC_R7: U13.D3(PE15)
LTDC_VSYNC: U13.H4(PI9) ; port LTDC.LTDC_VSYNC
MCO1: TP19.1 U13.A13(PA8) ; port PI_GPIO.MCO1  [project net EXP_GPIO4]
MCO2: TP1.1 U13.V2(PG2) ; port PI_GPIO.MCO2  [project net EXP_GPIO5]
NRST: U13.M3(NRST) ; port NRST
PA0_WKUP: U13.AB3(PA0) ; port PA0_WKUP
PA13: U13.N2(PA13) ; port PA13
PA14: U13.T2(PA14) ; port PA14
PI_GPIO7: U13.U1(PF3) ; port PI_GPIO.PI_GPIO7  [project net EXP_GPIO7]
PMIC_WAKEUP: U13.K2(PC13) ; port PMIC_WAKEUP
PWR_ON: R302.2 U13.R2(PWR_ON) ; port PWR_ON
SAI2_FSA: SB1.1 ; port AUDIO.SAI2_FSA
SAI2_FSAm: SB1.2 SB16.2 U13.F2(PI7)
SAI2_MCLKA: U13.D6(PE0) ; port AUDIO.SAI2_MCLKA
SAI2_SCKA: SB3.1 ; port AUDIO.SAI2_SCKA
SAI2_SCKAm: SB3.2 SB14.2 U13.F3(PI5)
SAI2_SDA: SB2.1 ; port AUDIO.SAI2_SDA
SAI2_SDAm: SB2.2 SB15.2 U13.F4(PI6)
SAI2_SDB: SB4.1 ; port AUDIO.SAI2_SDB
SAI2_SDBm: SB4.2 SB13.2 U13.Y10(PF11)
SDMMC1_CK: U13.D13(PC12) ; port uSD_CARD.SDMMC1_CK
SDMMC1_CMD: U13.D12(PD2) ; port uSD_CARD.SDMMC1_CMD
SDMMC1_D0: U13.D18(PC8)
SDMMC1_D1: U13.D17(PC9)
SDMMC1_D2: U13.D15(PC10)
SDMMC1_D3: U13.D16(PC11)
SDMMC2_CK: U13.C9(PE3) ; port WL_SDIO.SDMMC2_CK
SDMMC2_CMD: U13.A10(PG6) ; port WL_SDIO.SDMMC2_CMD
SDMMC2_D0: U13.C13(PB14)
SDMMC2_D1: U13.B12(PB15)
SDMMC2_D2: U13.A11(PB3)
SDMMC2_D3: U13.B13(PB4)
SDMMC3_CK: U13.B7(PG15) ; port PI_GPIO.SDMMC3_CK  [project net EXP_GPIO22]
SDMMC3_CMD: U13.A5(PF1) ; port PI_GPIO.SDMMC3_CMD  [project net EXP_GPIO23]
SDMMC3_D0: U13.D8(PF0) ; port PI_GPIO.SDMMC3_D0  [project net EXP_GPIO24]
SDMMC3_D1: U13.D9(PF4) ; port PI_GPIO.SDMMC3_D1  [project net EXP_GPIO25]
SDMMC3_D2: U13.D7(PF5) ; port PI_GPIO.SDMMC3_D2  [project net EXP_GPIO26]
SDMMC3_D3: U13.D10(PD7) ; port PI_GPIO.SDMMC3_D3  [project net EXP_GPIO27]
SPI5_MISO: U13.AC11(PF8) ; port PI_GPIO.SPI5_MISO  [project net EXP_GPIO9]
SPI5_MOSI: U13.AA14(PF9) ; port PI_GPIO.SPI5_MOSI  [project net EXP_GPIO10]
SPI5_NSS: U13.AA13(PF6) ; port PI_GPIO.SPI5_NSS  [project net EXP_GPIO8]
SPI5_SCK: U13.AB12(PF7) ; port PI_GPIO.SPI5_SCK  [project net EXP_GPIO11]
STLINK_SWCLK: TP5.1 U13.B20(JTCK-SWCLK) ; port STLINK_SWCLK
STLINK_SWDIO: TP3.1 U13.C20(JTMS-SWDIO) ; port STLINK_SWDIO
STUSB1600_IRQOUTn: U13.P4(PI11) ; port STUSB1600_IRQOUTn
TIM3_CH2: U13.B11(PC7) ; port PI_GPIO.TIM3_CH2  [project net EXP_GPIO13]
TIM4_CH2: U13.AA19(PD13) ; port PI_GPIO.TIM4_CH2  [project net EXP_GPIO12]
TIM5_CH2: U13.C4(PH11) ; port PI_GPIO.TIM5_CH2  [project net EXP_GPIO6]
UART4_RX: U13.Y16(PB2) ; port UART4_RX
UART4_TX: U13.Y7(PG11) ; port UART4_TX
USART2_CTS: U13.D14(PD3) ; port BT_UART.USART2_CTS
USART2_RTS: U13.B6(PD4) ; port BT_UART.USART2_RTS
USART2_RX: U13.D2(PD6) ; port BT_UART.USART2_RX
USART2_TX: U13.A7(PD5) ; port BT_UART.USART2_TX
USART3_CTS: U13.AA10(PB13) ; port PI_GPIO.USART3_CTS  [project net EXP_GPIO16]
USART3_RTS: U13.AB9(PG8) ; port PI_GPIO.USART3_RTS  [project net EXP_GPIO17]
USART3_RX: U13.AC5(PB12) ; port PI_GPIO.USART3_RX  [project net EXP_GPIO15]
USART3_TX: U13.Y3(PB10) ; port PI_GPIO.USART3_TX  [project net EXP_GPIO14]
USB1_N: U13.AB17(USB_DM1) ; port USB_DM1
USB1_P: U13.AC17(USB_DP1) ; port USB_DP1
USB2_N: U13.AB16(USB_DM2) ; port USB_DM2
USB2_P: U13.AC16(USB_DP2) ; port USB_DP2
USB_PWR_CC1: U13.V4(PA4) ; port USB_PWR_CC1
USB_PWR_CC2: U13.V3(PA5) ; port USB_PWR_CC2
uSD_DETECT: U13.D11(PB7) ; port uSD_CARD.uSD_DETECT
WL_HOST_WAKE: U13.B8(PD0) ; port WL_HOST_WAKE
WL_REG_ON: U13.B3(PH4) ; port WL_REG_ON
NetC87_1: C87.1 R73.1 R302.1 X6.1(EN)
NetC90_1: C90.1 U13.L2(PC14-OSC32_IN) X4.2(X2)
NetC91_1: C91.1 R71.2 X4.1(X1)
NetC92_2: C92.2 TP22.1 U13.M4(NRST_CORE)
NetC300_2: C300.2 R304.2 X6.4(VDD)
NetR38_1: R38.1 U13.K23(DDR_ZQ)
NetR44_2: R44.2 U13.AB18(USB_RREF)
NetR71_1: R71.1 U13.L1(PC15-OSC32_OUT)
NetSB9_1: SB9.1 SB12.2 U13.T3(PDR_ON_CORE)
NetSB10_1: SB10.1 SB11.2 U13.R3(PDR_ON)
NetTP10_1: TP10.1 U13.K20(DDR_DTO0)
NetTP13_1: TP13.1 U13.L21(DDR_DTO1)
NetTP14_1: TP14.1 U13.Y19(DDR_ATO)
NetTP23_1: TP23.1 U13.N3(PWR_LP)

Not connected (* = marked no-connect by the designer): U13 A21(DDR_DQ20)* A22(DDR_DQ23)* AA20(DDR_DQM3)* AA22(DDR_DQ31)* AA23(DDR_DQ30)* AB20(DDR_DQ27)* AB21(DDR_DQ26)* AB22(DDR_DQS3P)* AB23(DDR_DQS3N)* AC19(OTG_VBUS)* AC21(DDR_DQ29)* AC22(DDR_DQ28)* B21(DDR_DQ19)* B22(DDR_DQ16)* B23(DDR_DQS2N)* C22(DDR_DQS2P)* C23(DDR_DQM2)* D21(DDR_DQ22)* D22(DDR_DQ17)* D23(DDR_DQ18)* E23(DDR_DQ21)* P20(DDR_A15)* Y22(DDR_DQ25)* Y23(DDR_DQ24)*

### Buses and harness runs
bus ARD_A[0..5] = port ARD_A[0..5]
bus ARD_D[0..15] = port ARD_D[0..15]
bus BOOT[0..2] = port BOOT[0..2]
bus ETH_RXD[0..3]
bus ETH_TXD[0..3]
bus LTDC_B[0..7]
bus LTDC_G[0..7]
bus LTDC_R[0..7]
bus SDMMC1_D[0..3]
bus SDMMC2_D[0..3]

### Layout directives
differential pair: USB1_N, USB1_P, USB2_N, USB2_P

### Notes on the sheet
- WLAN-BLUETOOTH
- AUDIO
- ETHERNET
- uSD CARD
- MISC
- USB Host - TypeC
- GPIO & ARDUINO
- or I2C2_SDA
- or I2C2_SCL
- ST LINK
- HDMI
- DSI LCD
- POWER - PMIC

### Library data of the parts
C68 = MCD-00006: as C61 on sheet Power_PMIC
C87 C88 = MCD-00674: Capacitor, MLCC, 6.8pF, 50V, NPO, +-0.25pF, 0402, T=0.5mm; Manufacturer_Part_Number: CC0402CRNPO9BN6R8; Manufacturer: YAGEO; Provided_By: SUBCO; Initial_Board_Reference: MB1319
C90 C91 = MCD-00674: Capacitor, MLCC, 6.8pF, 50V, NPO, +-0.25pF, 0402, T=0.5mm; Manufacturer_Part_Number: CC0402CRNPO9BN6R8; Manufacturer: YAGEO; Provided_By: SUBCO; Initial_Board_Reference: MB1319; Path: ws/MCD_ApplicationBoards/Lists/MCDPARTSdatabase; Item Type: Item
C92 C300 = MCD-00011: Capacitor, MLCC, 10nF, 16V, X7R, 10%, 0402, T=0.5mm; Manufacturer_Part_Number: CC0402KRX7R7BB103; Manufacturer: YAGEO; Provided_By: SUBCO; Initial_Board_Reference: MB1274
R1 R2 R5 R7 R166 R167 = MCD-00068: Resistor,1K5,0402,1%,1/16W; Manufacturer_Part_Number: RC0402FR-071K5L; Manufacturer: YAGEO; Provided_By: SUBCO; Initial_Board_Reference: mb1274
R38 = MCD-00120: Resistor,240R,0402,1%,1/16W; Manufacturer_Part_Number: RC0402FR-07240RL; Manufacturer: YAGEO; Provided_By: SUBCO; Initial_Board_Reference: mb1262
R40 R300 R302 = MCD-00053: Resistor,10K,0402,1%,1/16W; Manufacturer_Part_Number: RC0402FR-0710KL; Manufacturer: YAGEO; Provided_By: SUBCO; Initial_Board_Reference: MB1274
R44 = MCD-00185: Resistor,3K,0402,1%,1/16W; Manufacturer_Part_Number: RC0402FR-073KL; Manufacturer: YAGEO; Provided_By: SUBCO
R71 R73 = MCD-00052: as R6 on sheet Power_PMIC
R303 = MCD-00061: Resistor,1K,0402,1%,1/16W; Manufacturer_Part_Number: RC0402FR-071KL; Manufacturer: YAGEO; Provided_By: SUBCO; Initial_Board_Reference: mb1274
R304 = MCD-00358: Resistor,10R,0402,1%,1/16W; Manufacturer_Part_Number: RC0402FR-0710RL; Manufacturer: YAGEO; Provided_By: SUBCO
SB1-SB4 SB9 SB10 = MCD-00071: Solder Bridge ON; Part_Type: Mechanical; Manufacturer: YAGEO; Manufacturer_Part_Number: RC0603JR-070RL; Provided_By: SUBCO; Initial_Board_Reference: mb1274
SB11-SB16 = MCD-00072: Solder Bridge OFF; Part_Type: Mechanical; Manufacturer: YAGEO; Manufacturer_Part_Number: RC0603JR-070RL; Provided_By: SUBCO; Initial_Board_Reference: mb1274
TP1-TP5 TP8 TP9 TP19 TP22 TP23 = MCD-00074: Test Point 1mm; Part_Type: Mechanical; Initial_Board_Reference: MB1274
TP10 TP13 TP14 = MCD-00631: Test Point 0.6mm; Part_Type: Mechanical; Initial_Board_Reference: mb1264
U13 = MCD-02020: as U13 on sheet Power_MPU
X4 = MCD-01479: Crystal 32.768kHz, 6pF, -+20PPM, R=80K, SMD; Part_Type: Crystal_Osc; Manufacturer_Part_Number: NX2012SA 32.768KHz EXS00A-MU00527; Manufacturer: NDK; Provided_By: SUBCO; Initial_Board_Reference: MB1373; Path: ws/MCD_ApplicationBoards/Lists/MCDPARTSdatabase; Item Type: Item
X6 = MCD-01627: Oscillator 24Mhz, +-50ppm, Vcc:3.3V typ (1.62V min), square wave: [0.1Vcc;0.9Vcc], Enable pin; Part_Type: Crystal_Osc; Manufacturer_Part_Number: NZ2016SH 24MHz END4869F; Manufacturer: NDK; Provided_By: SUBCO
